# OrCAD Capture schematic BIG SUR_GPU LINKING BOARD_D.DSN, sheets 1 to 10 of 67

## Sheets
1 P01  Cover Page: title: Big Sur; rev: D; company: Quanta
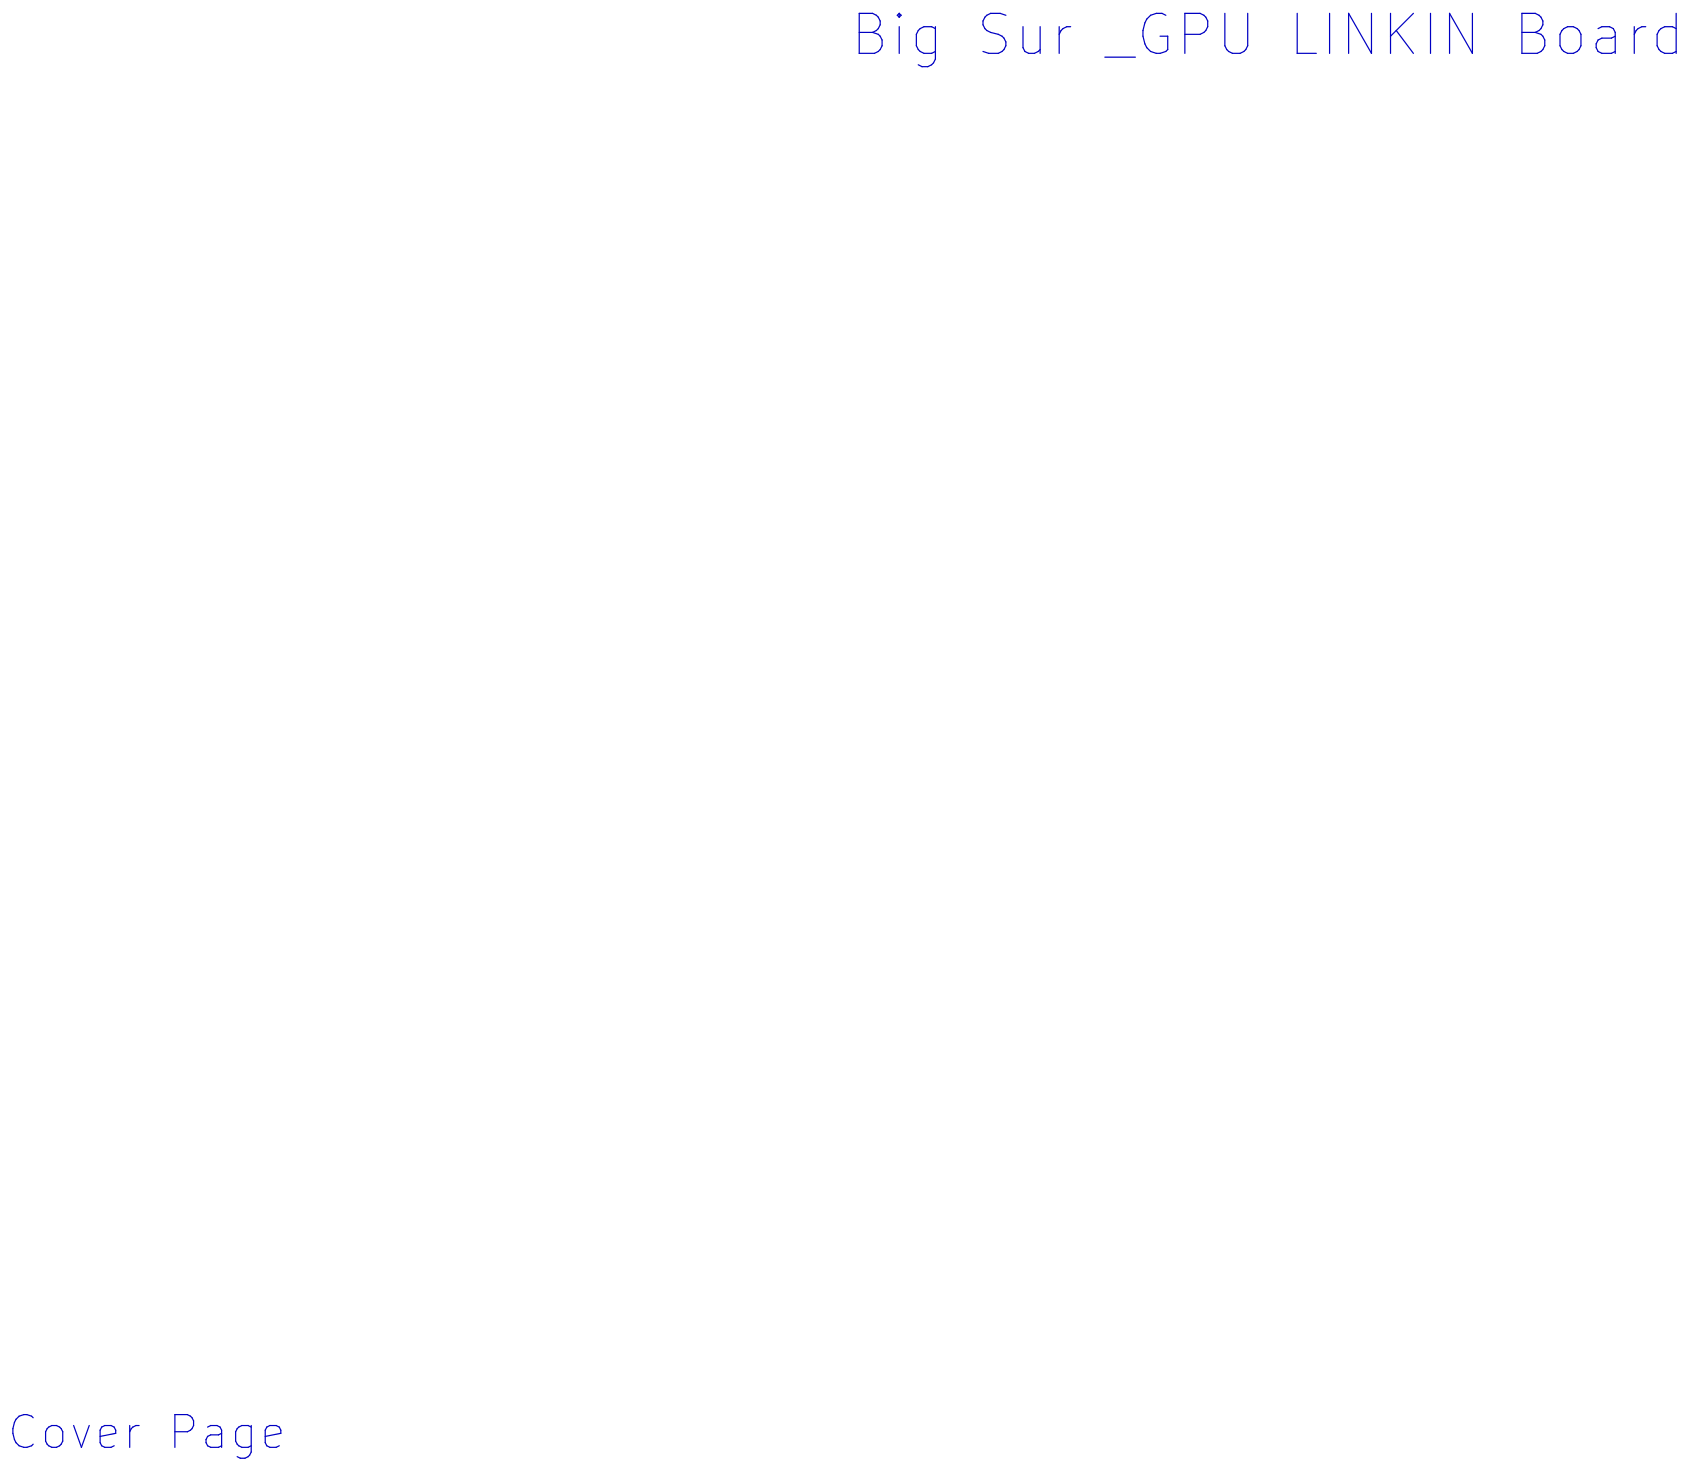
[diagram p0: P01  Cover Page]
2 P02  Index
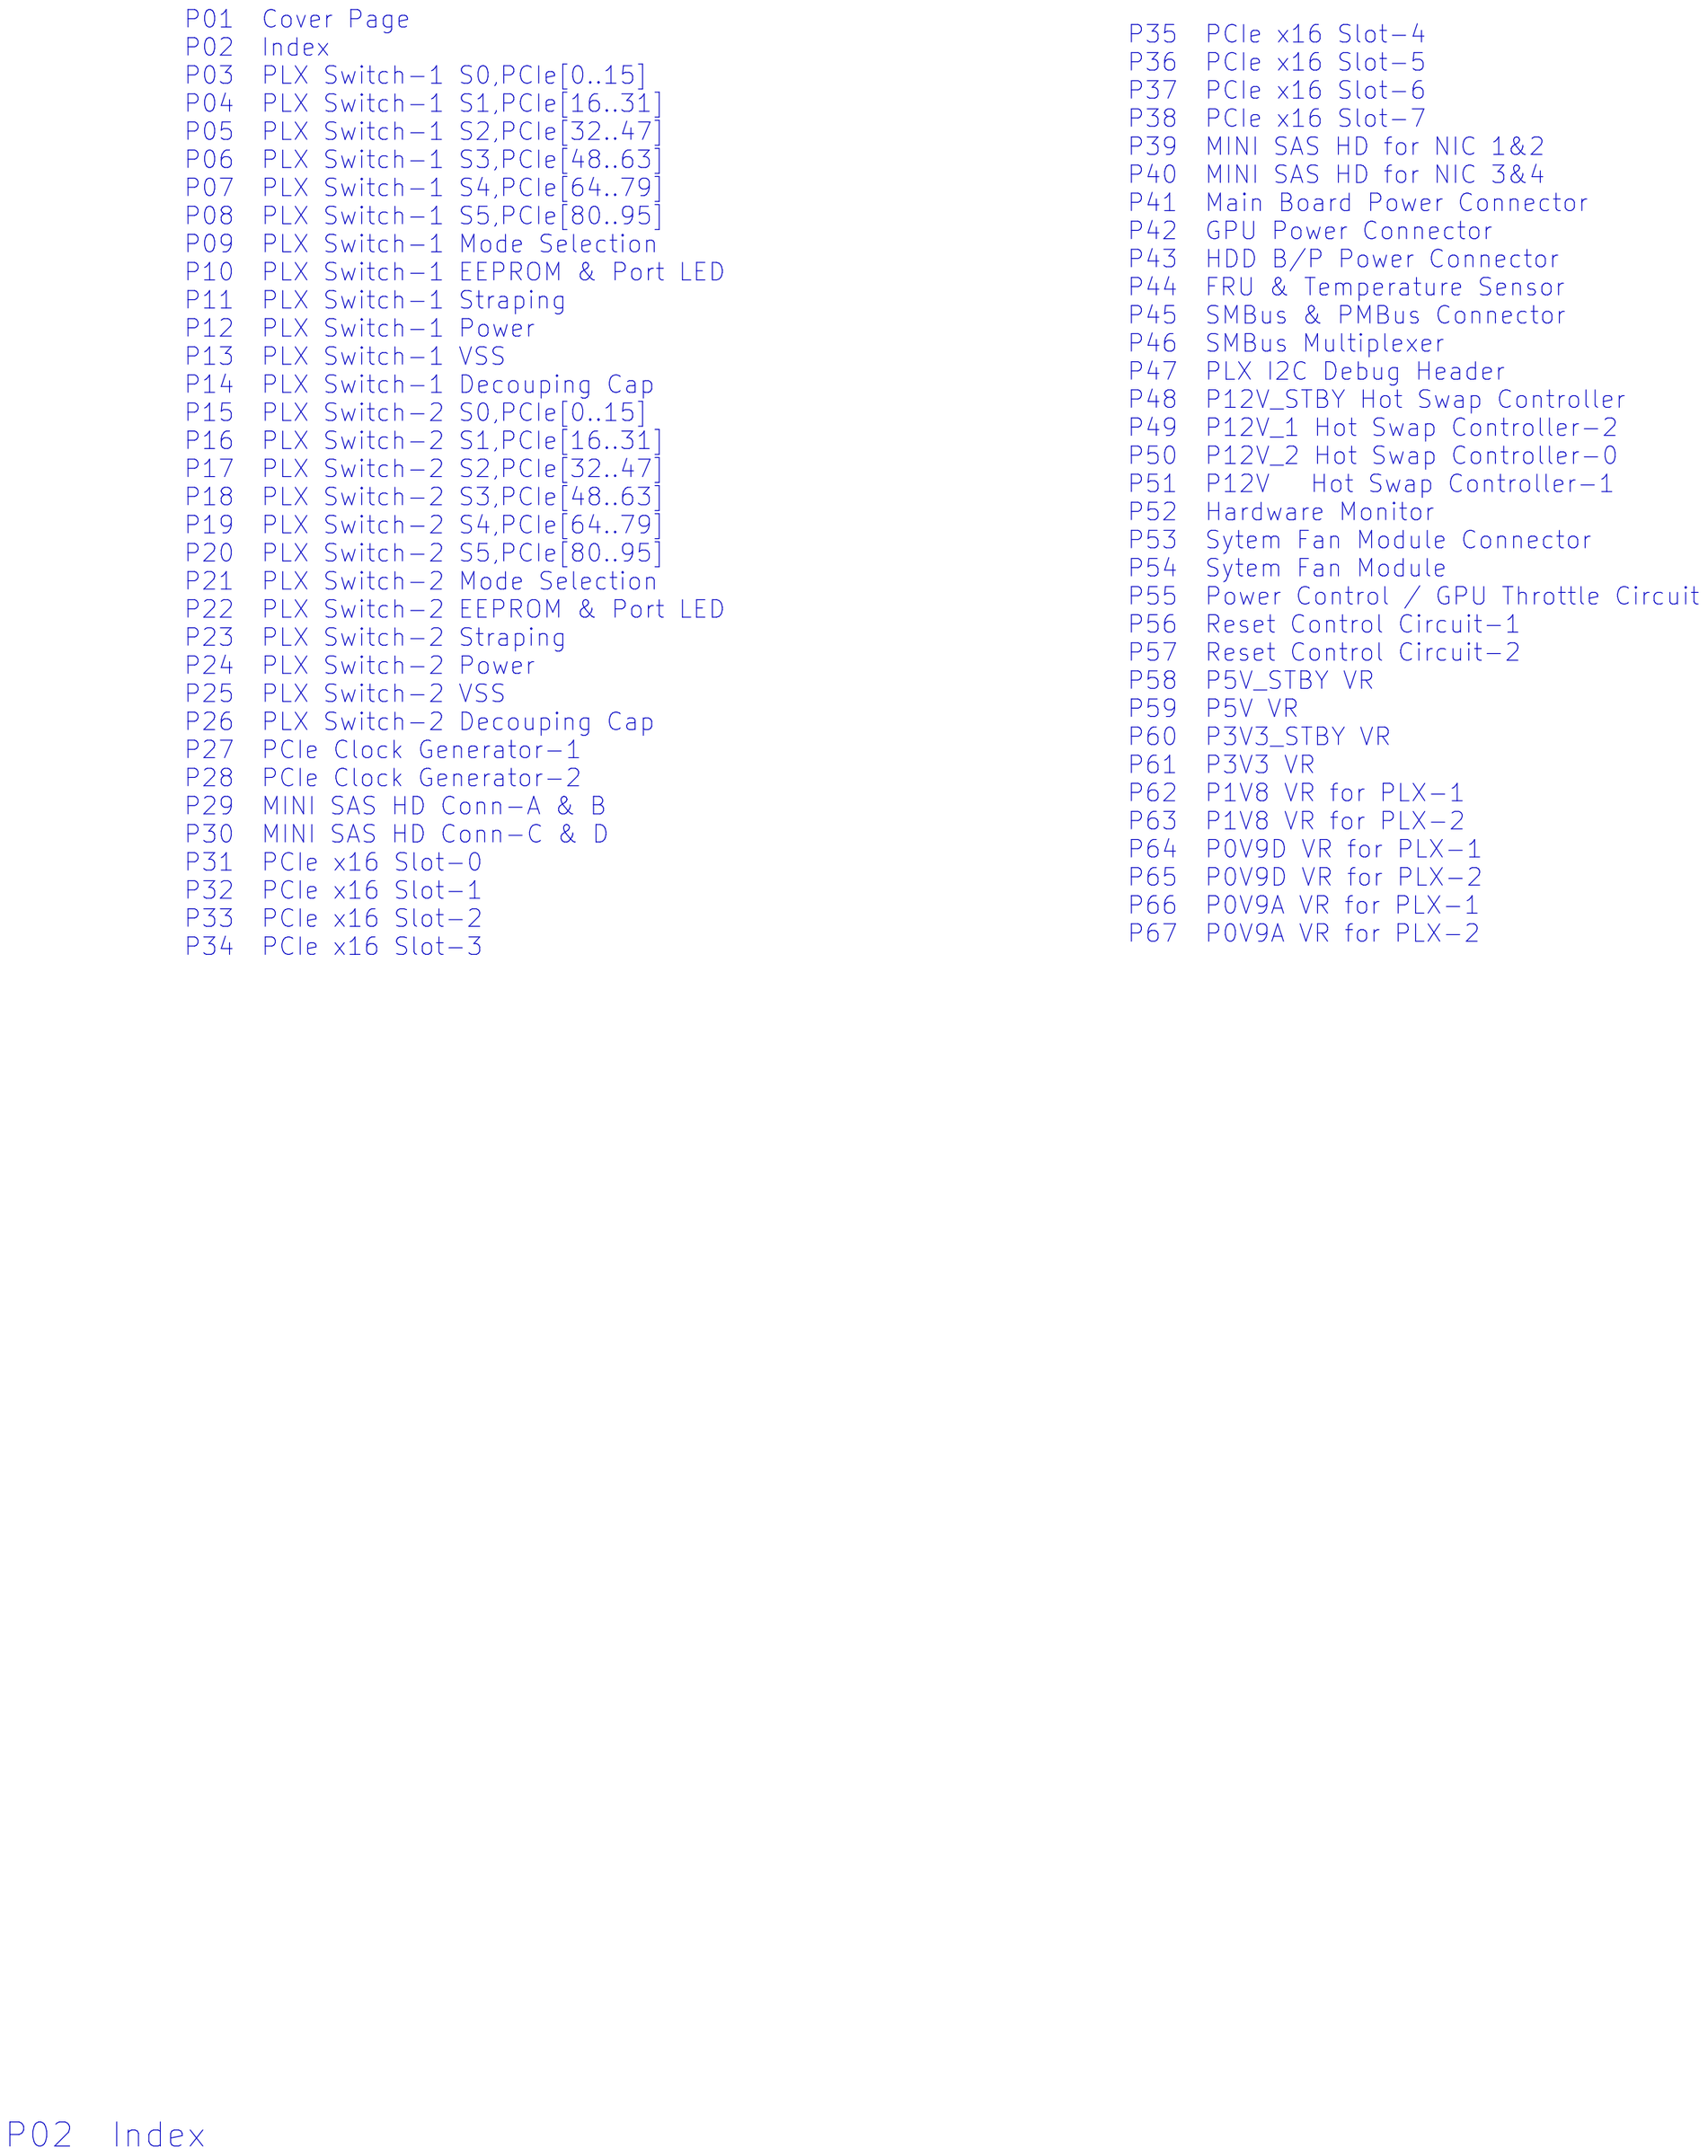
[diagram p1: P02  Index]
3 P03  PLX Switch-1 S0: size C
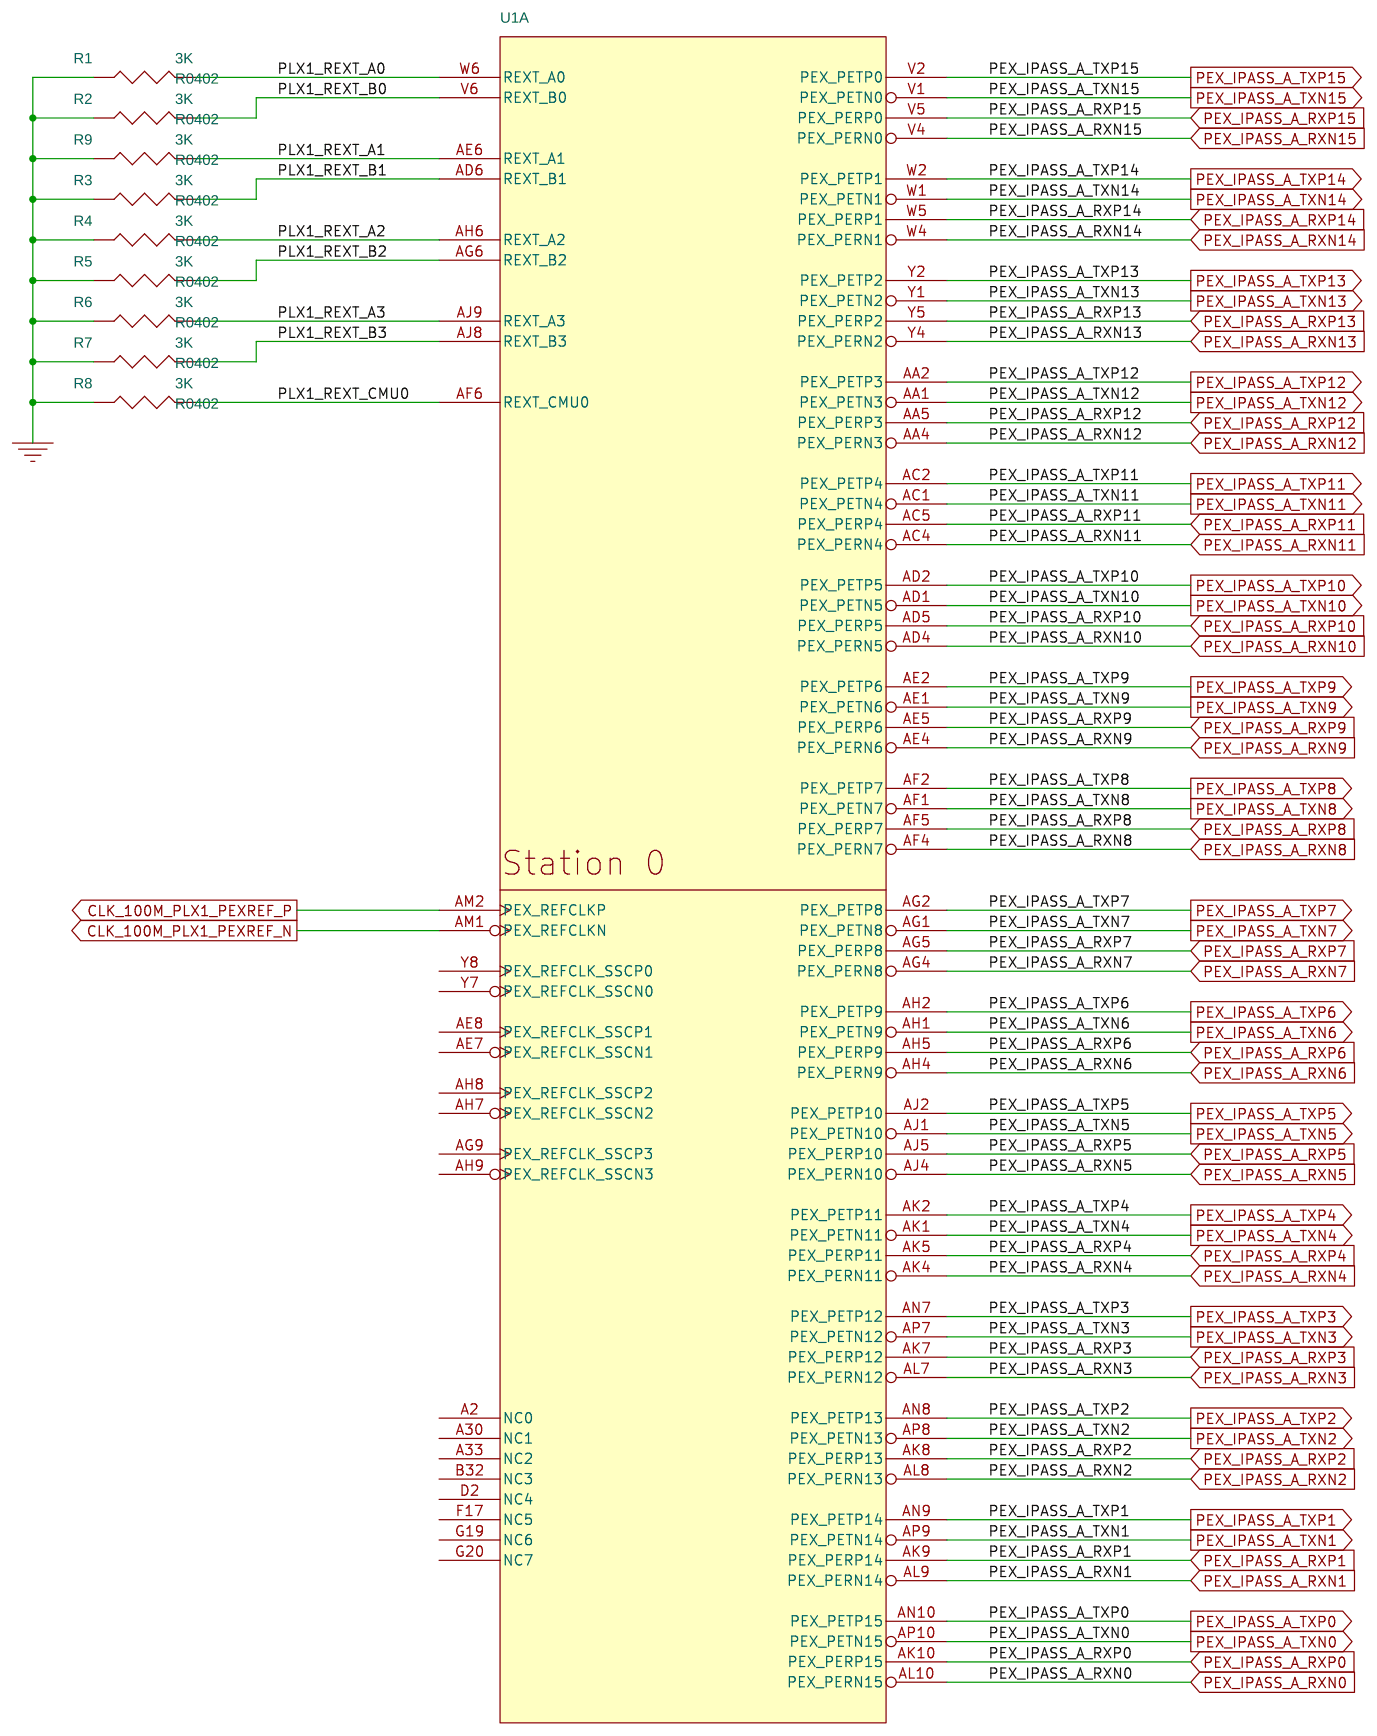
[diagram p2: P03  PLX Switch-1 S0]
4 P04  PLX Switch-1 S1: size C
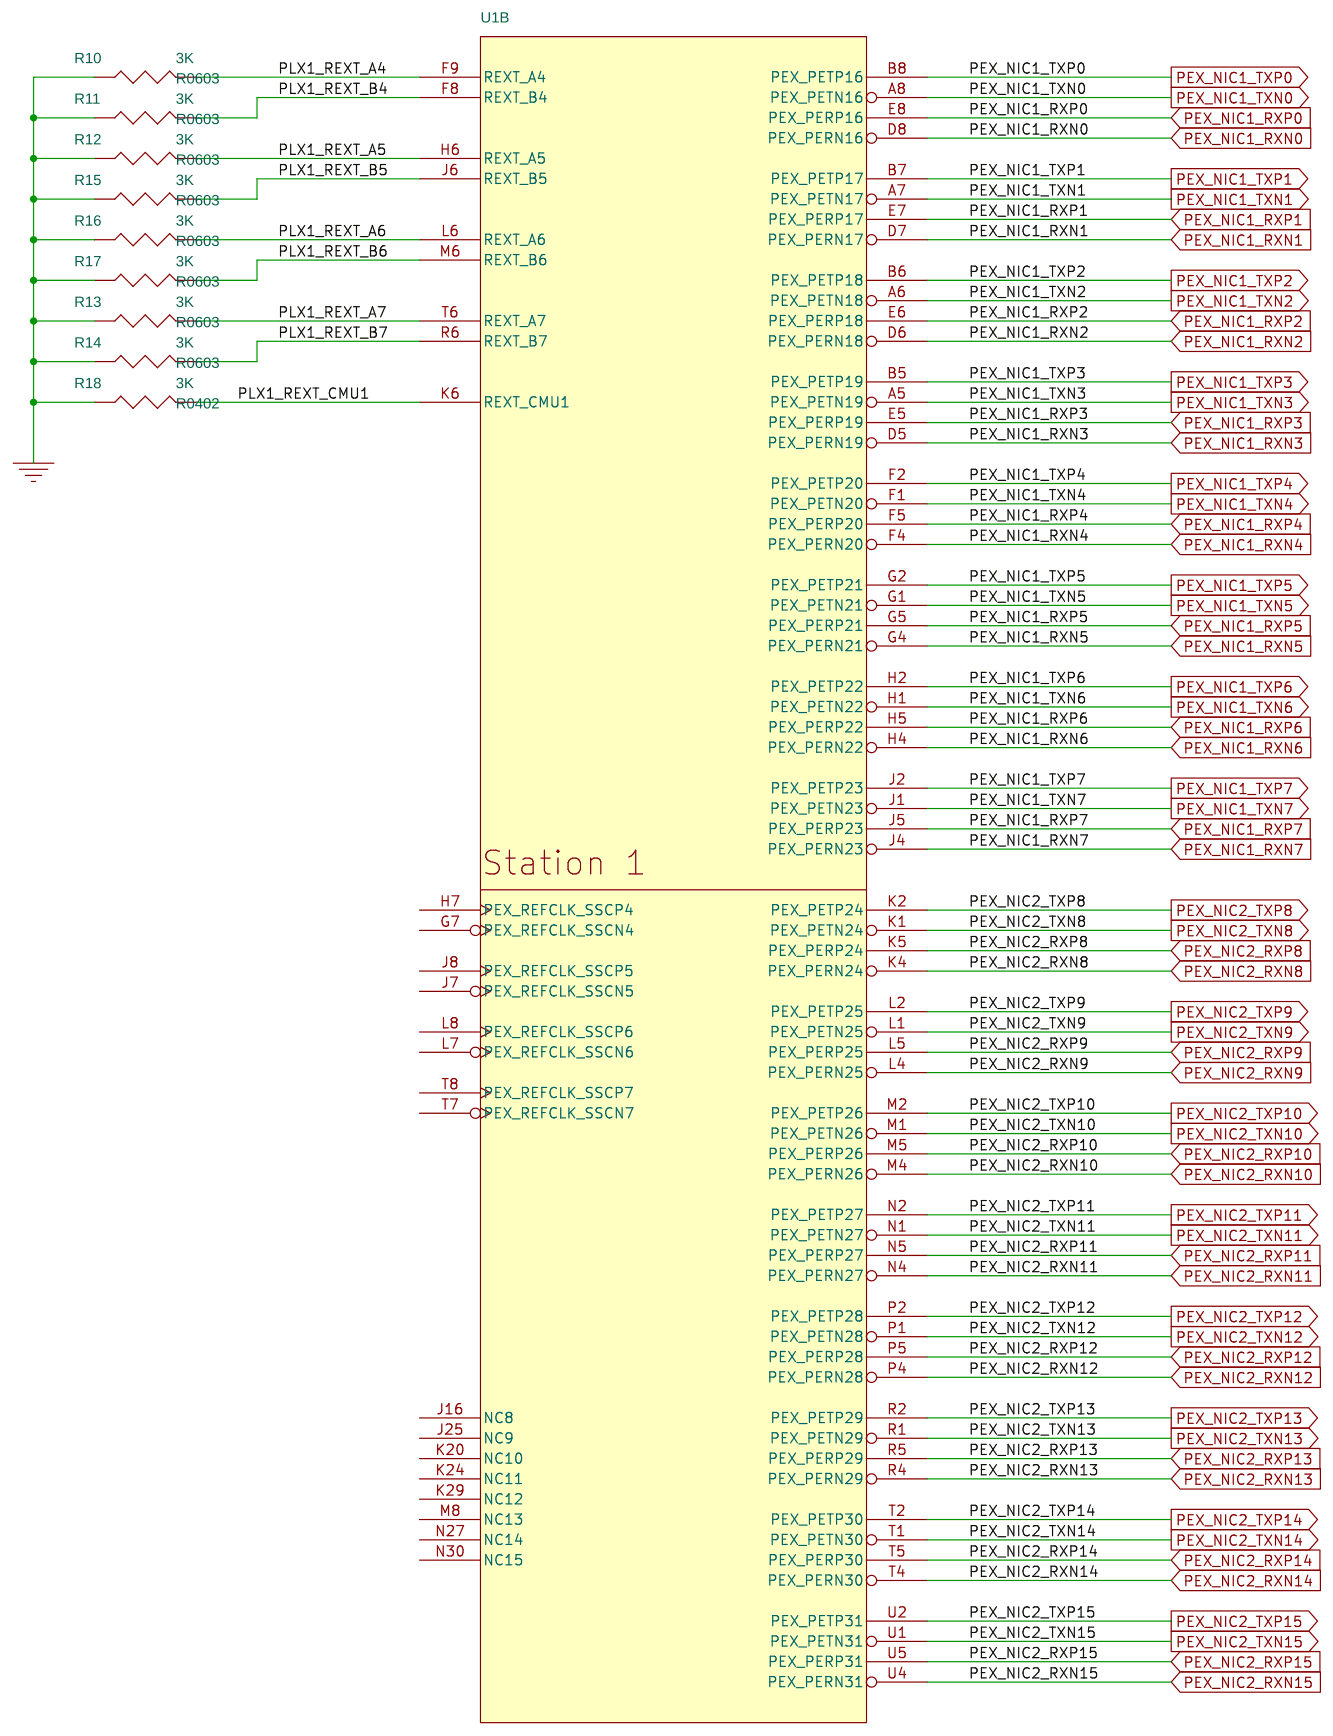
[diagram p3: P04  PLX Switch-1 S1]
5 P05  PLX Switch-1 S2: size C
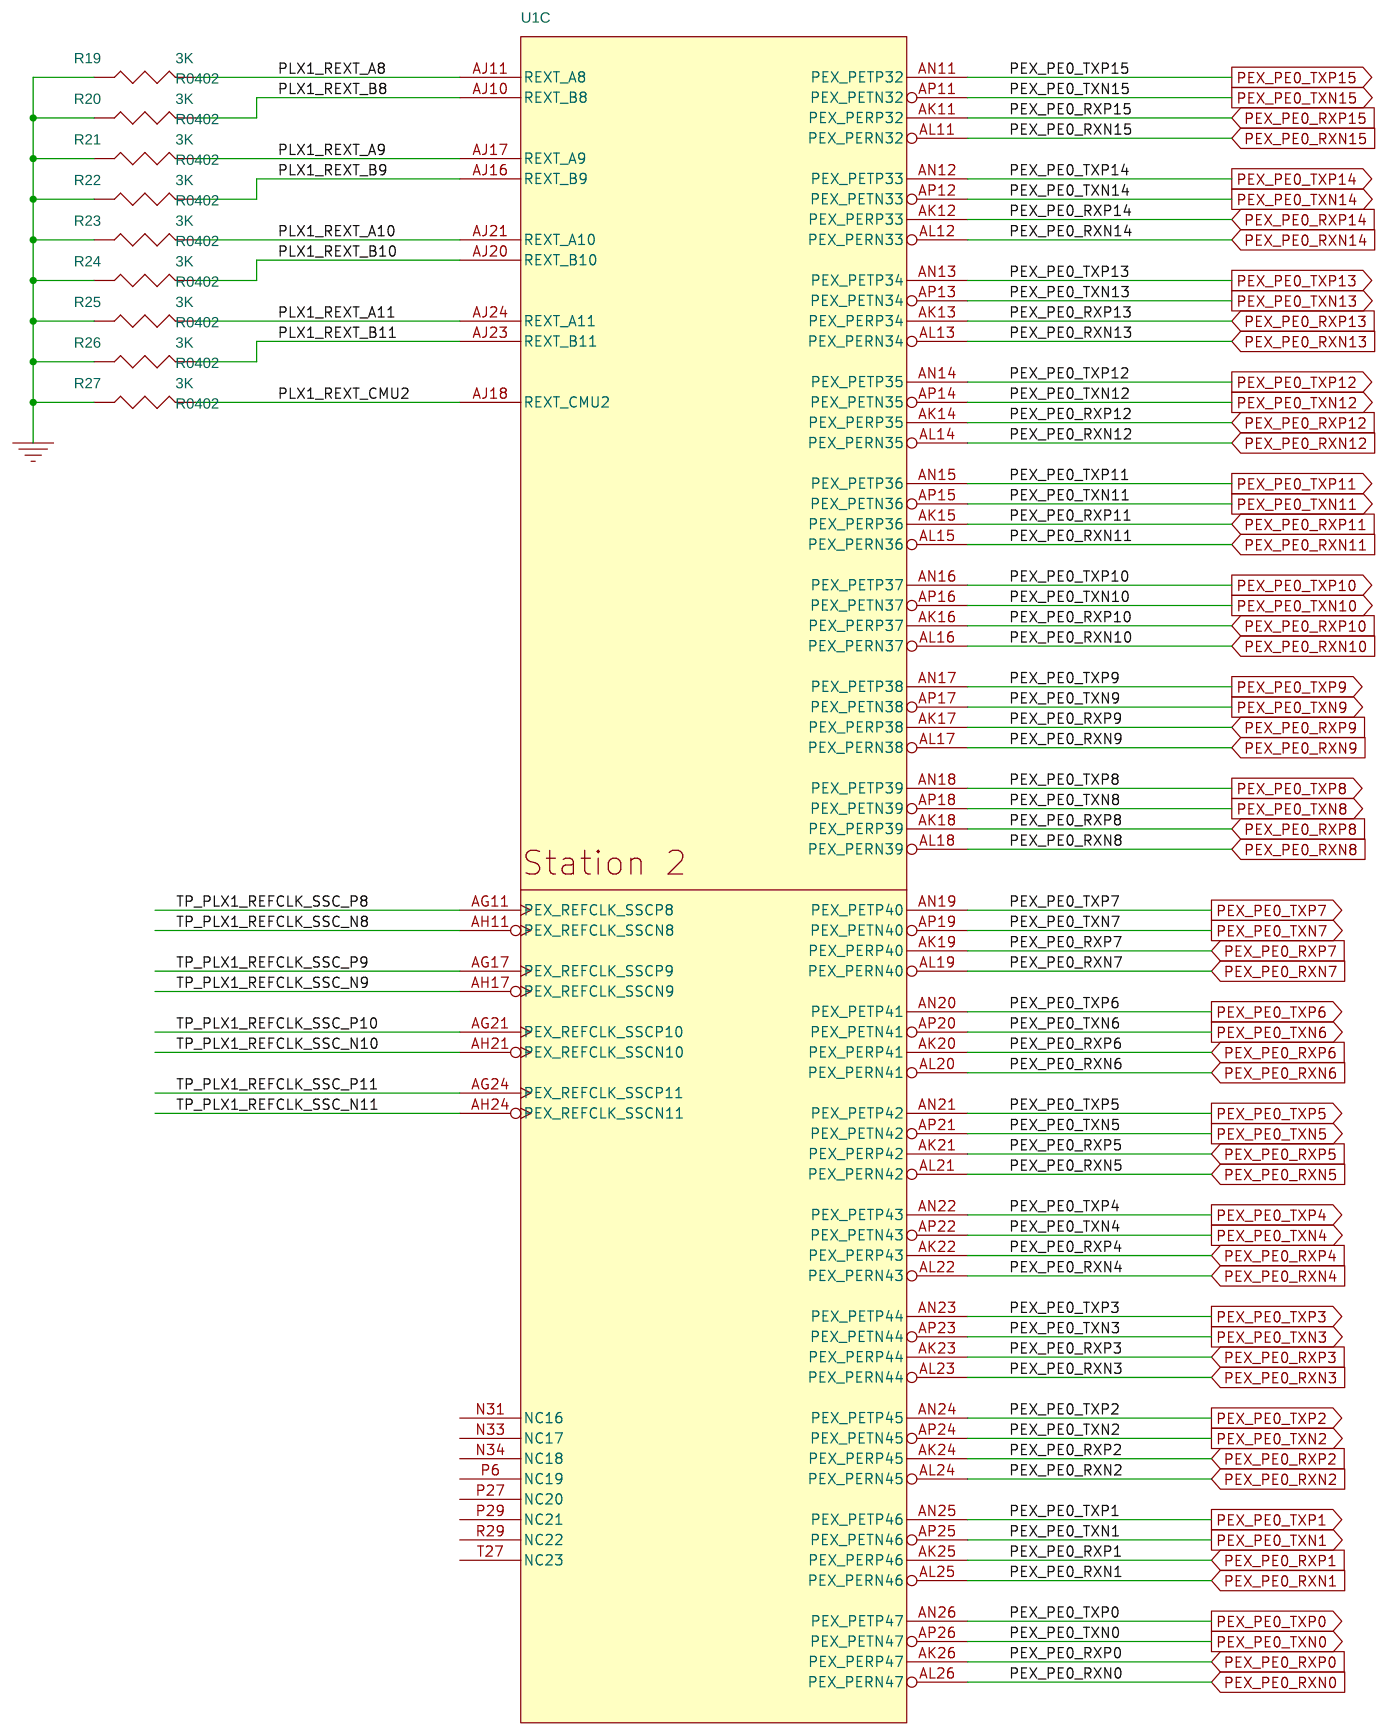
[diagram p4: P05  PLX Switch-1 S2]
6 P06  PLX Switch-1 S3: size Custom
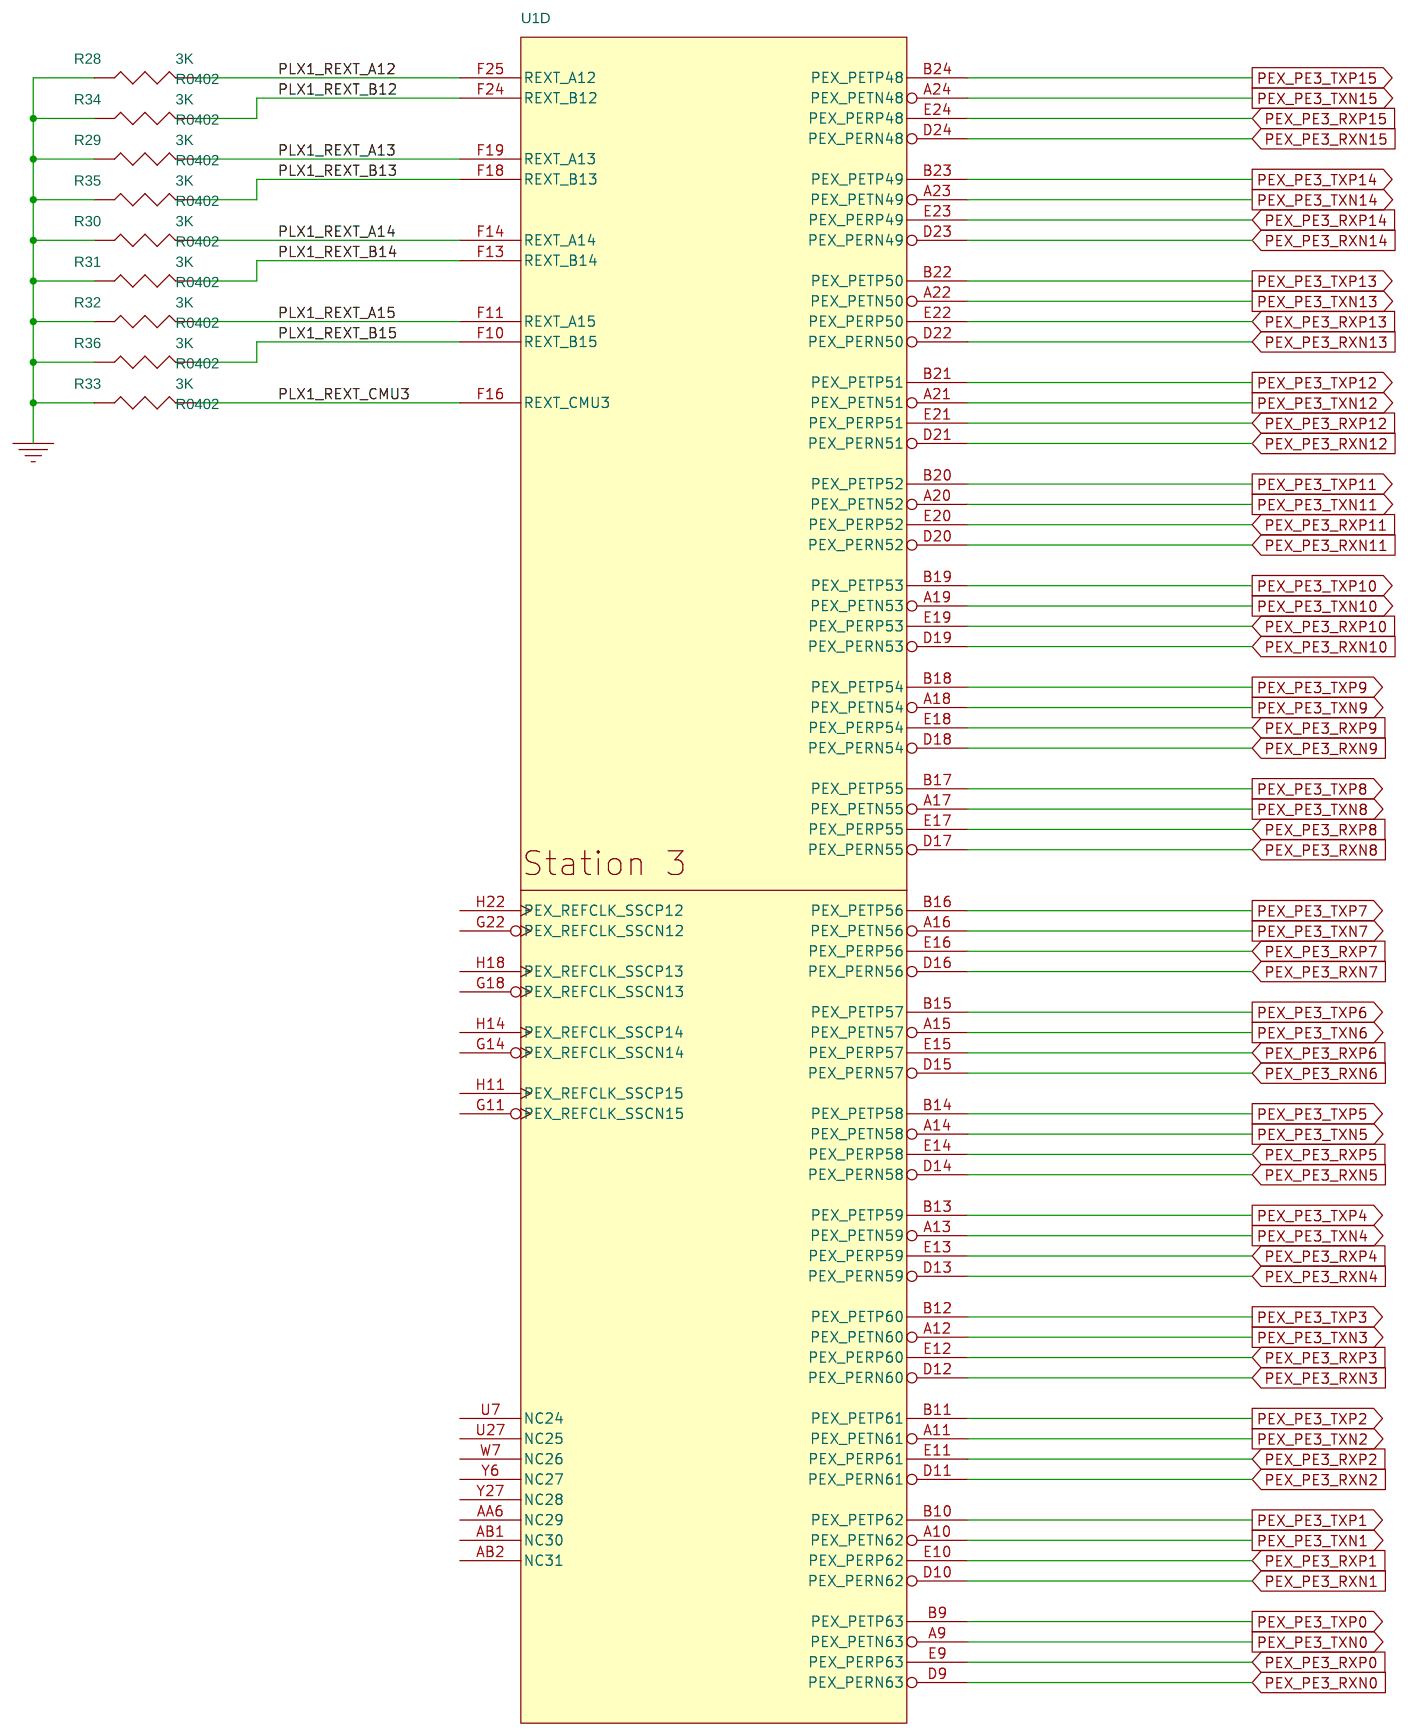
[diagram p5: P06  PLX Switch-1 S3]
7 P07  PLX Switch-1 S4: size Custom
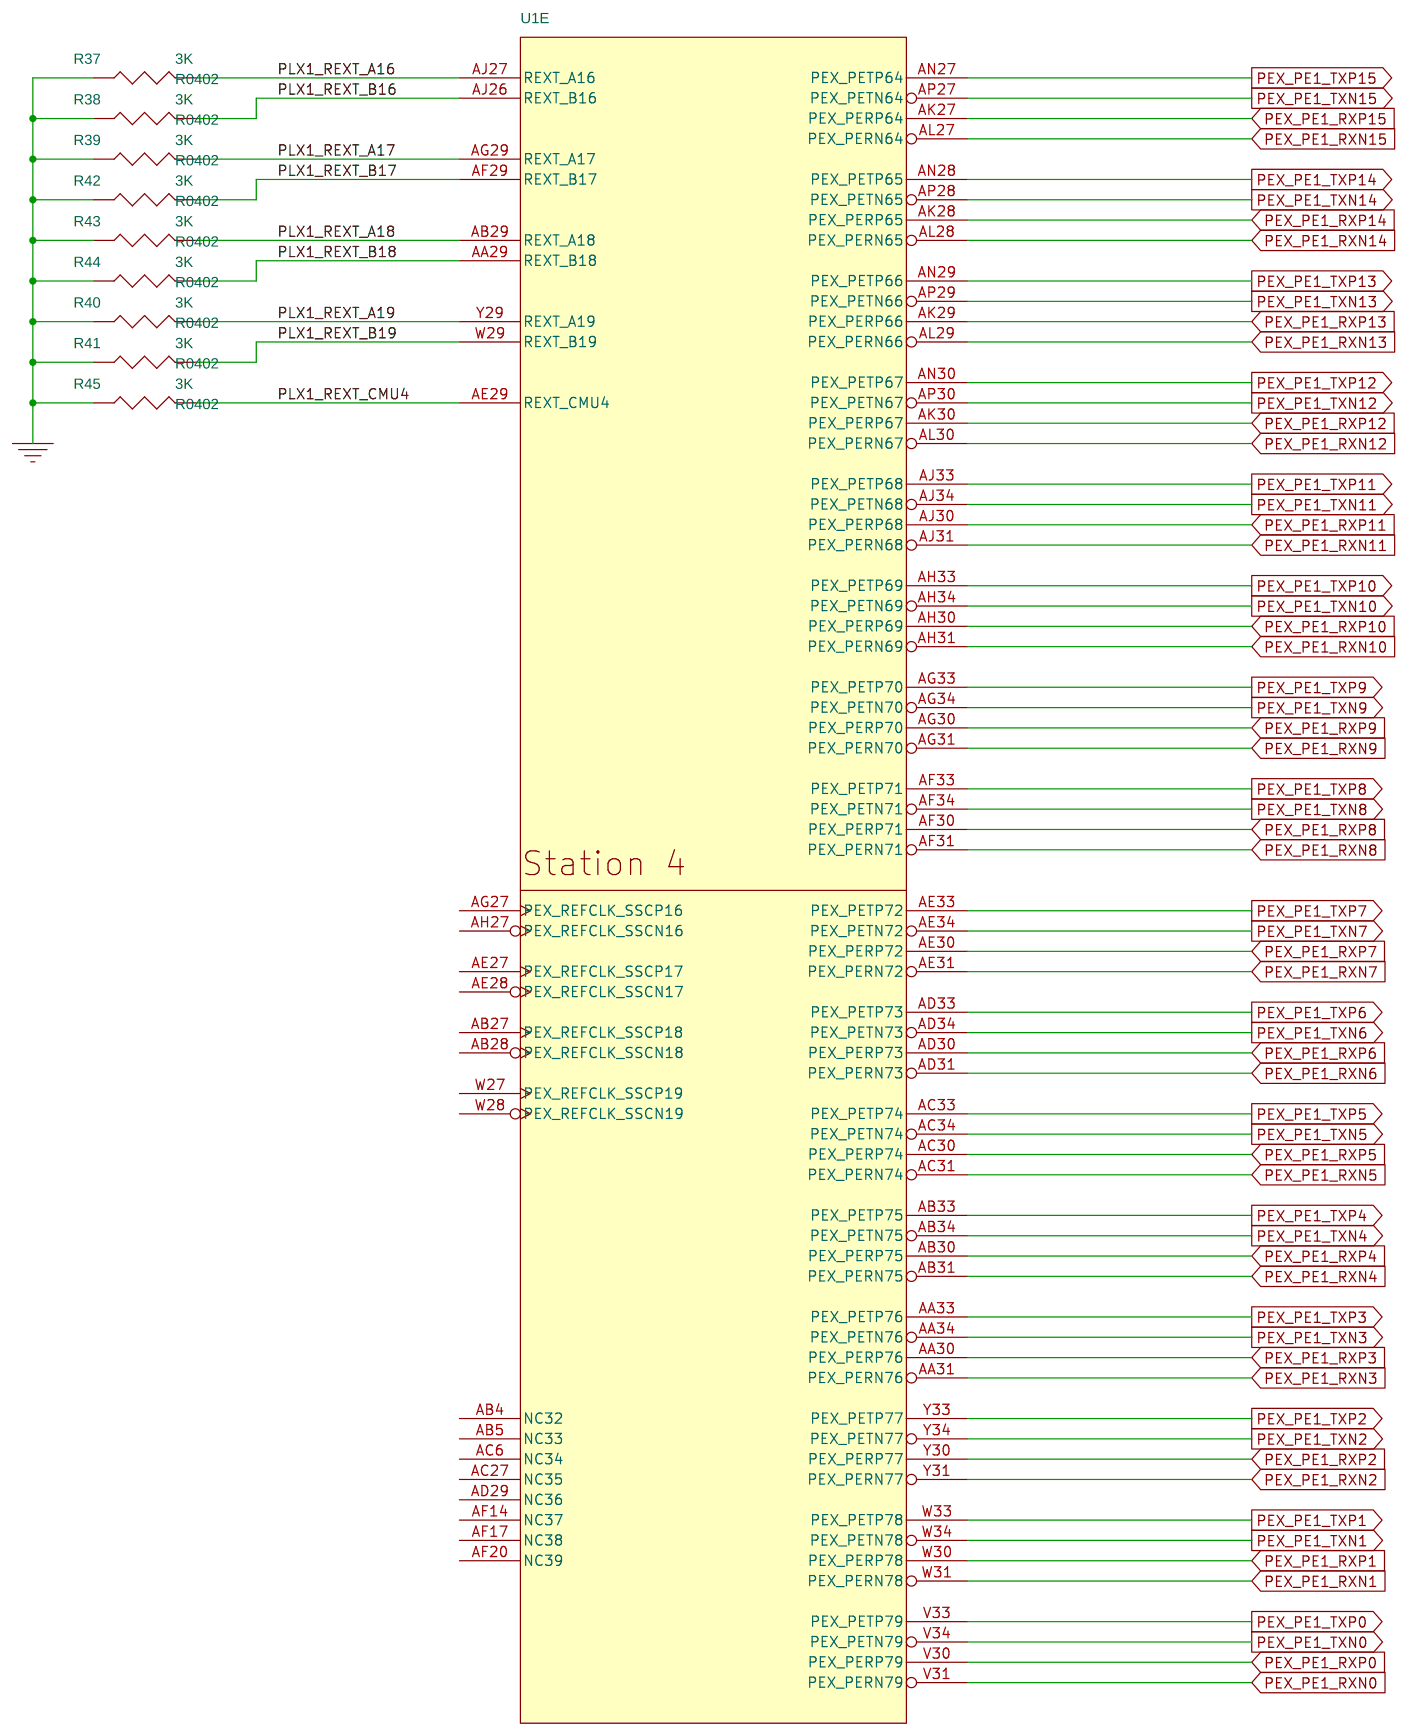
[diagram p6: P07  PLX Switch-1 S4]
8 P08  PLX Switch-1 S5: size Custom
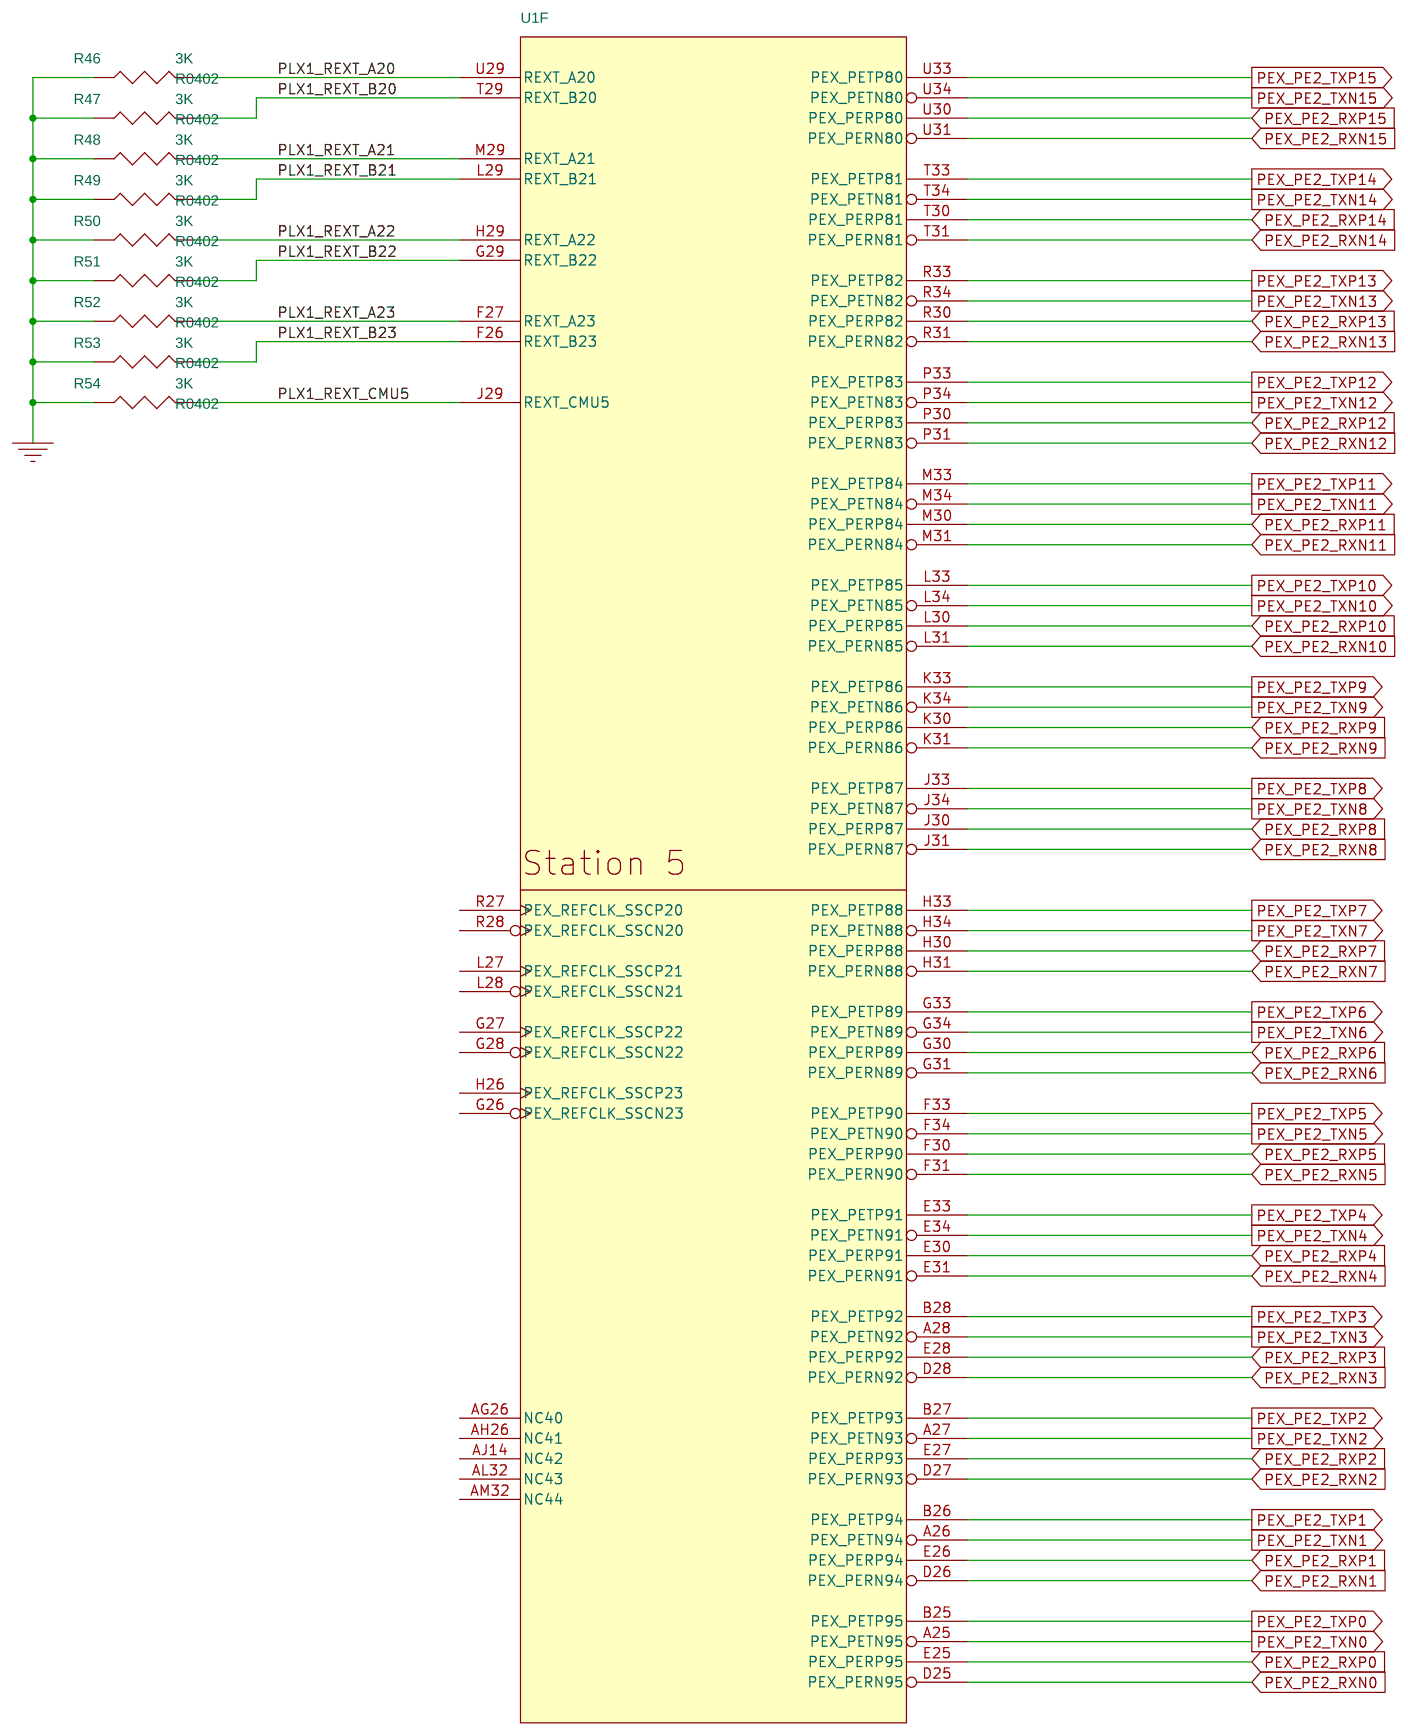
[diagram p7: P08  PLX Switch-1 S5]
9 P09  PLX Switch-1 Mode Select: size C
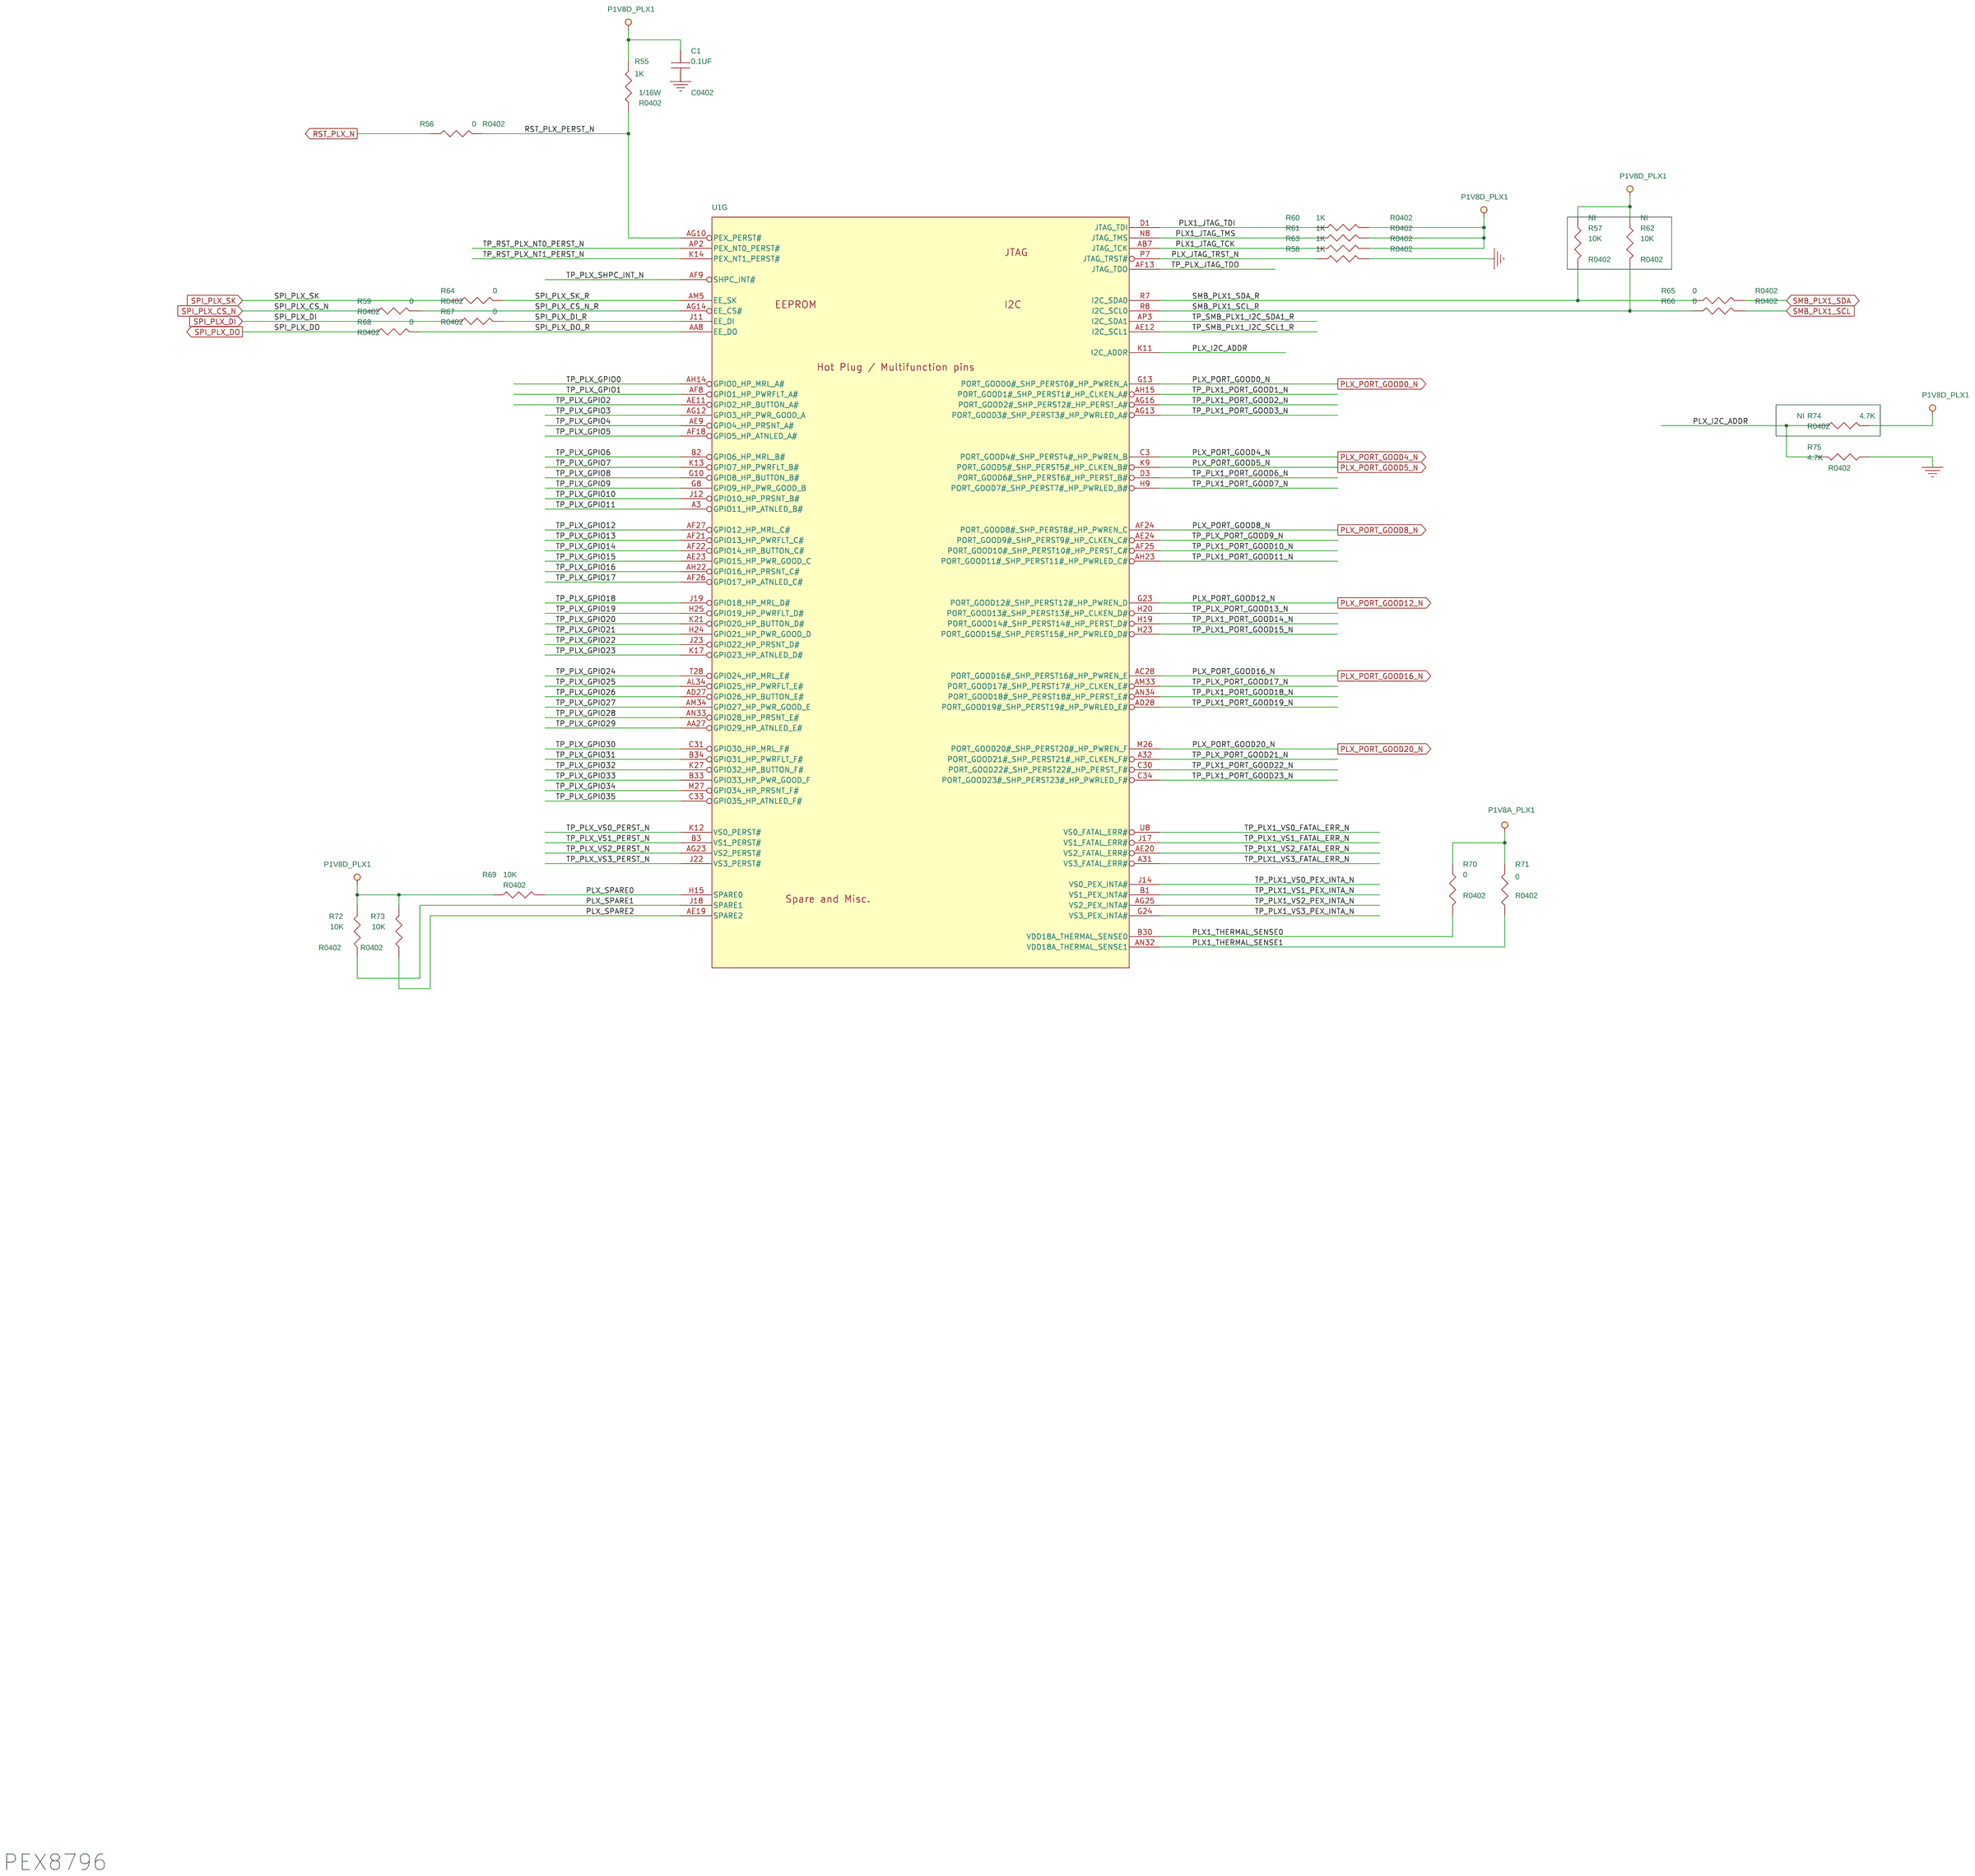
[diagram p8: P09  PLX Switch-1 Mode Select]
10 P10  PLX SW-1 EEPROM & Port LED: size C
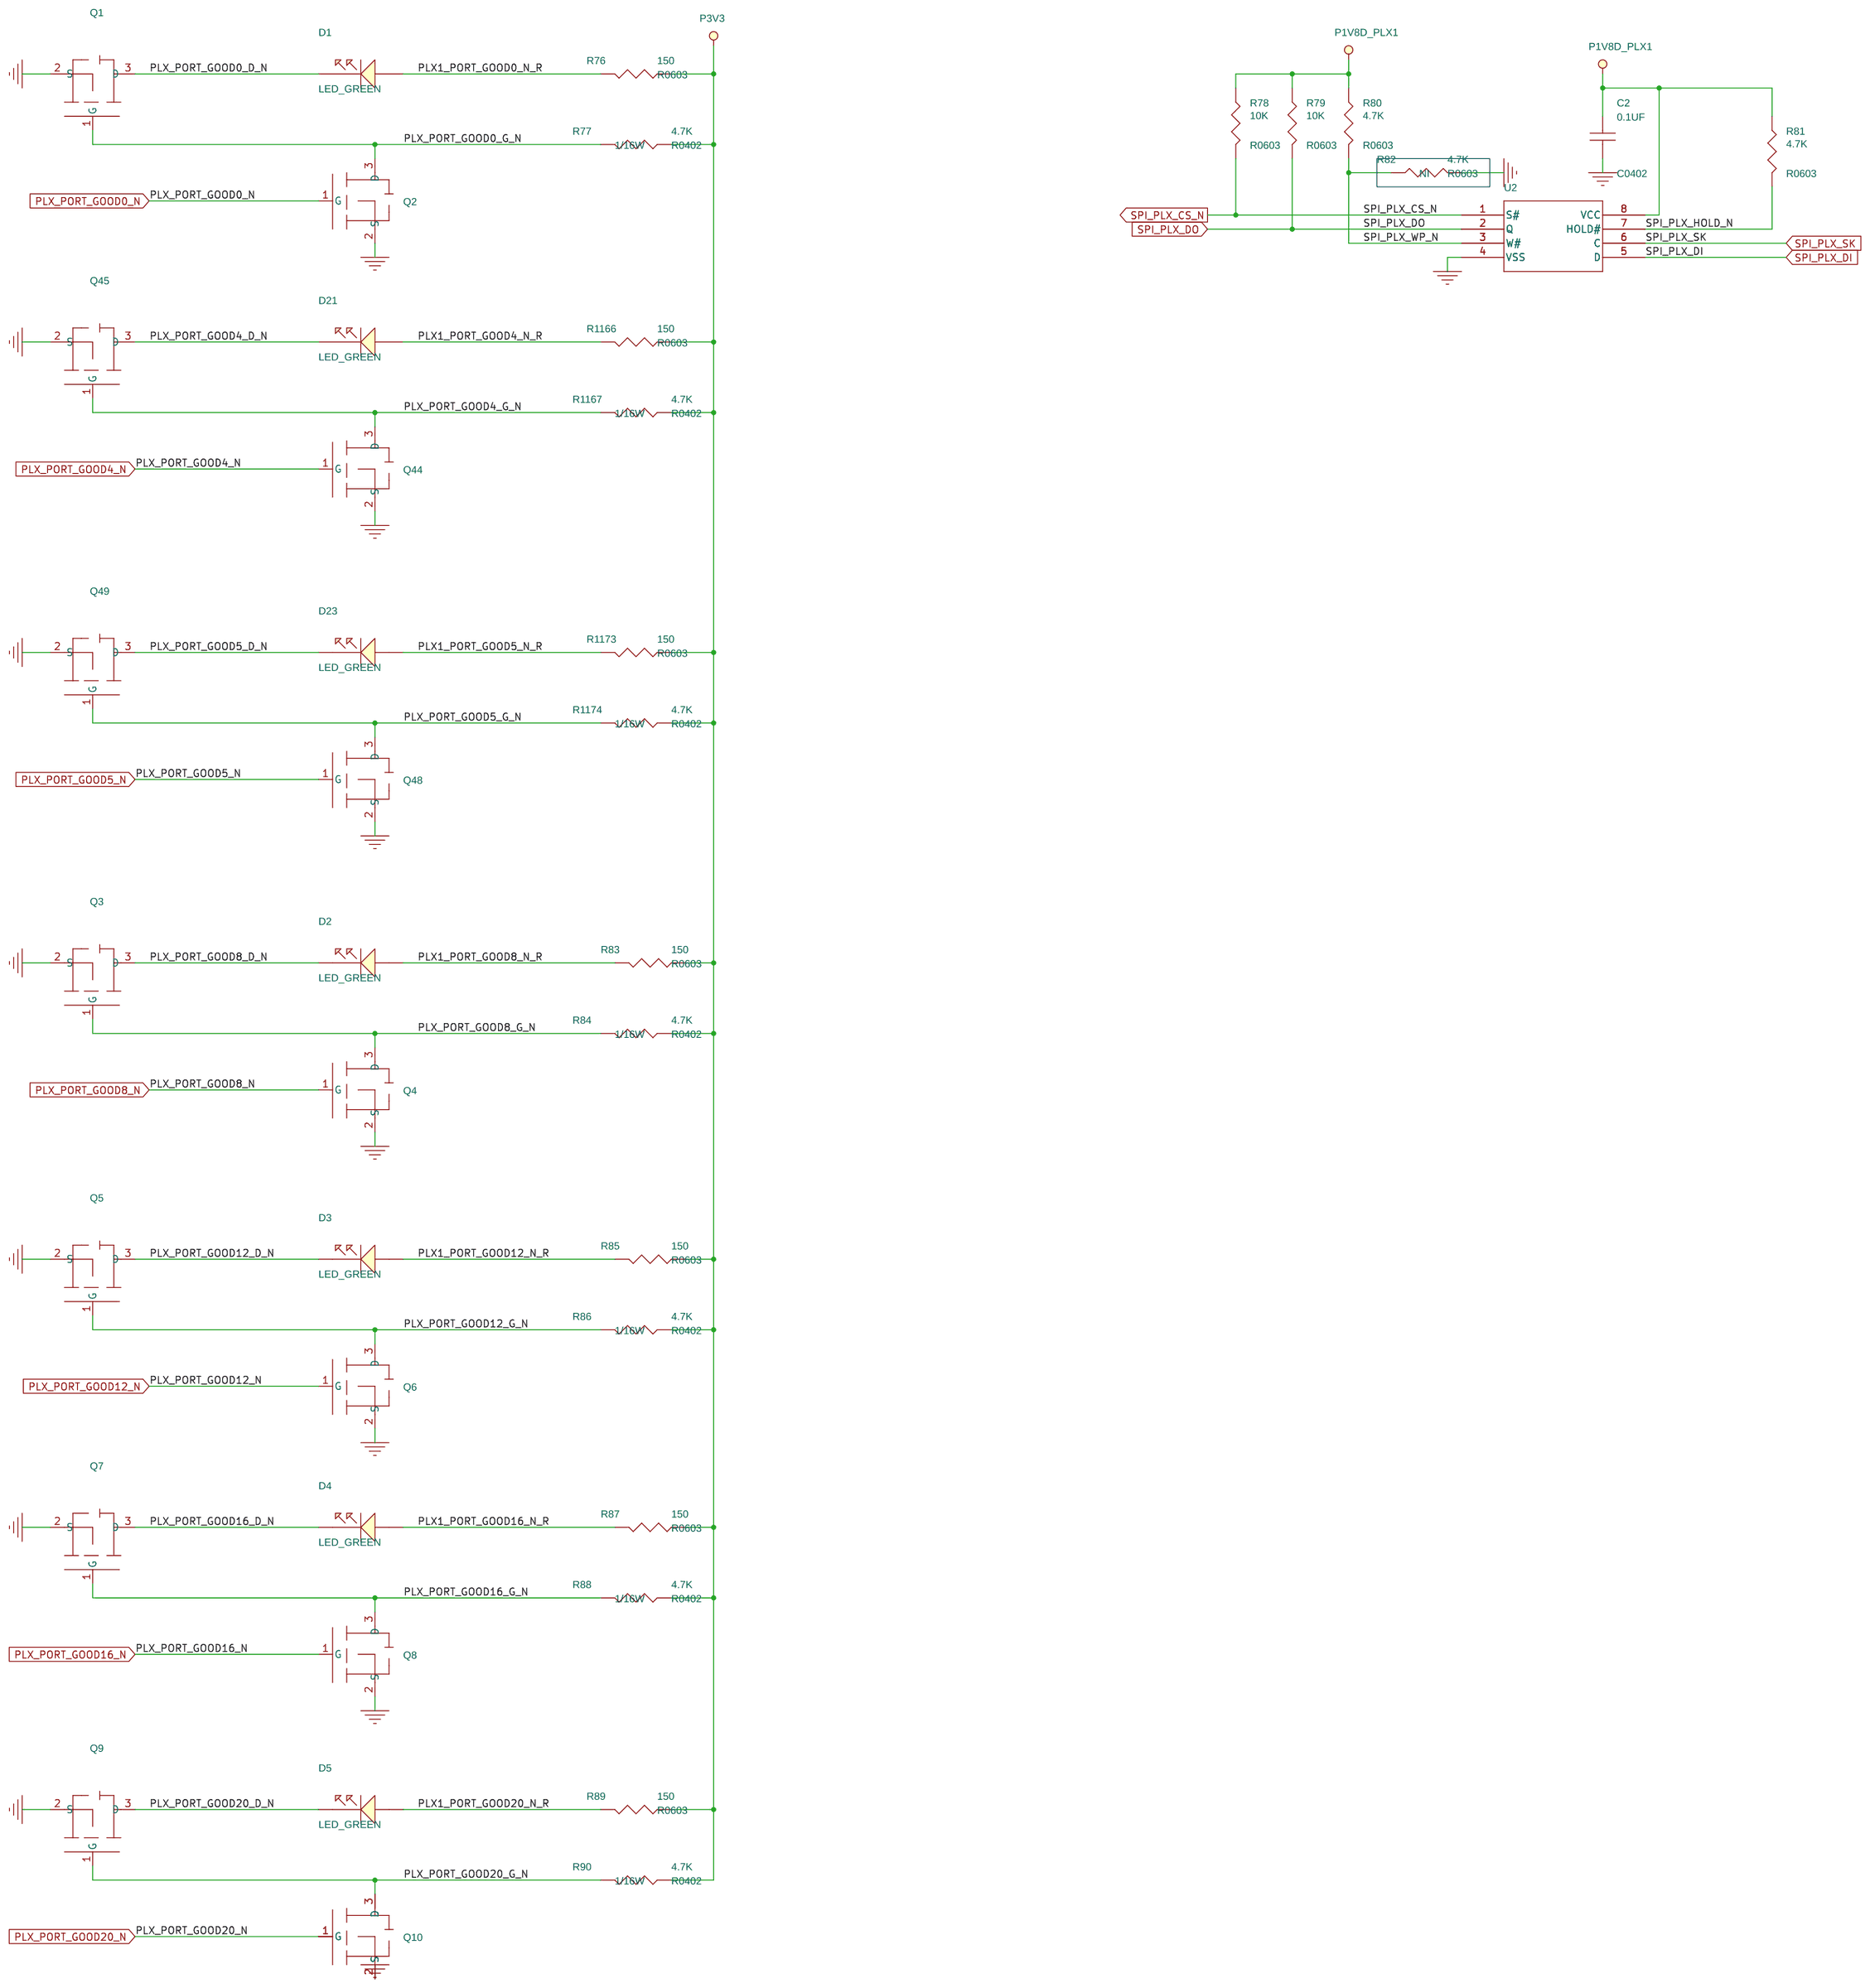
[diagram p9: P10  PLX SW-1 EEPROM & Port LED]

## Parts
sheet P03  PLX Switch-1 S0
R1  3K  [R0402]
R2  3K  [R0402]
R3  3K  [R0402]
R4  3K  [R0402]
R5  3K  [R0402]
R6  3K  [R0402]
R7  3K  [R0402]
R8  3K  [R0402]
R9  3K  [R0402]
sheet P04  PLX Switch-1 S1
R10  3K  [R0603]
R11  3K  [R0603]
R12  3K  [R0603]
R13  3K  [R0603]
R14  3K  [R0603]
R15  3K  [R0603]
R16  3K  [R0603]
R17  3K  [R0603]
R18  3K  [R0402]
sheet P05  PLX Switch-1 S2
R19  3K  [R0402]
R20  3K  [R0402]
R21  3K  [R0402]
R22  3K  [R0402]
R23  3K  [R0402]
R24  3K  [R0402]
R25  3K  [R0402]
R26  3K  [R0402]
R27  3K  [R0402]
sheet P06  PLX Switch-1 S3
R28  3K  [R0402]
R29  3K  [R0402]
R30  3K  [R0402]
R31  3K  [R0402]
R32  3K  [R0402]
R33  3K  [R0402]
R34  3K  [R0402]
R35  3K  [R0402]
R36  3K  [R0402]
sheet P07  PLX Switch-1 S4
R37  3K  [R0402]
R38  3K  [R0402]
R39  3K  [R0402]
R40  3K  [R0402]
R41  3K  [R0402]
R42  3K  [R0402]
R43  3K  [R0402]
R44  3K  [R0402]
R45  3K  [R0402]
sheet P08  PLX Switch-1 S5
R46  3K  [R0402]
R47  3K  [R0402]
R48  3K  [R0402]
R49  3K  [R0402]
R50  3K  [R0402]
R51  3K  [R0402]
R52  3K  [R0402]
R53  3K  [R0402]
R54  3K  [R0402]
sheet P09  PLX Switch-1 Mode Select
C1  0.1UF  [C0402]
R55  1K  [R0402]
R56  0  [R0402]
R57  10K  [R0402]
R58  1K  [R0402]
R59  0  [R0402]
R60  1K  [R0402]
R61  1K  [R0402]
R62  10K  [R0402]
R63  1K  [R0402]
R64  0  [R0402]
R65  0  [R0402]
R66  0  [R0402]
R67  0  [R0402]
R68  0  [R0402]
R69  10K  [R0402]
R70  0  [R0402]
R71  0  [R0402]
R72  10K  [R0402]
R73  10K  [R0402]
R74  4.7K  [R0402]
R75  4.7K  [R0402]
sheet P10  PLX SW-1 EEPROM & Port LED
C2  0.1UF  [C0402]
D1  LED_GREEN  [LED_1221B]
D2  LED_GREEN  [LED_1221B]
D3  LED_GREEN  [LED_1221B]
D4  LED_GREEN  [LED_1221B]
D5  LED_GREEN  [LED_1221B]
D21  LED_GREEN  [LED_1221B]
D23  LED_GREEN  [LED_1221B]
Q1  BSS138LT1G  [SOT23_123]
Q2  BSS138LT1G  [SOT23_123]
Q3  BSS138LT1G  [SOT23_123]
Q4  BSS138LT1G  [SOT23_123]
Q5  BSS138LT1G  [SOT23_123]
Q6  BSS138LT1G  [SOT23_123]
Q7  BSS138LT1G  [SOT23_123]
Q8  BSS138LT1G  [SOT23_123]
Q9  BSS138LT1G  [SOT23_123]
Q10  BSS138LT1G  [SOT23_123]
Q44  BSS138LT1G  [SOT23_123]
Q45  BSS138LT1G  [SOT23_123]
Q48  BSS138LT1G  [SOT23_123]
Q49  BSS138LT1G  [SOT23_123]
R76  150  [R0603]
R77  4.7K  [R0402]
R78  10K  [R0603]
R79  10K  [R0603]
R80  4.7K  [R0603]
R81  4.7K  [R0603]
R82  4.7K  [R0603]
R83  150  [R0603]
R84  4.7K  [R0402]
R85  150  [R0603]
R86  4.7K  [R0402]
R87  150  [R0603]
R88  4.7K  [R0402]
R89  150  [R0603]
R90  4.7K  [R0402]
R1166  150  [R0603]
R1167  4.7K  [R0402]
R1173  150  [R0603]
R1174  4.7K  [R0402]
U2  IC  [SOIC8XH]
sheet P11  PLX Switch-1 Straping
U1  PLX  [BGA1156]  (sections A,B,C,D,E,F,G,H,I,J,K,L)

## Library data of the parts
R1-R9 R18-R56 R58-R61 R63-R73 R75 R77 R84 R86 R88 R90 R1167 R1174 = R: Part_Type: *LF_Resistor; WATTAGE: 1/16W
R10-R17 R76 R78-R81 R83 R85 R87 R89 R1166 R1173 = R: Part_Type: *LF_Resistor; WATTAGE: 1/10W
C1 C2 = CAP_NP: Part_Type: *LF_C0402
R57 R62 R74 = R: Not_insert: NI; Part_Type: *LF_Resistor; WATTAGE: 1/16W
D1-D5 D21 D23 = LED_12: Part_Type: Semiconductor
Q1-Q10 Q44 Q45 Q48 Q49 = BSS123: Part_Type: *LF_Semiconductor
R82 = R: Not_insert: NI; Part_Type: *LF_Resistor; WATTAGE: 1/10W
U2 = M95512RMN6TP: Part_Type: *LF_Chipset
U1 = PEX8796AA80BIG: Part_Type: *LF_Chipset

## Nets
GND: C1.2 C2.2 Q1.2(S) Q2.2(S) Q3.2(S) Q4.2(S) Q5.2(S) Q6.2(S) Q7.2(S) Q8.2(S) Q9.2(S) Q10.2(S) Q44.2(S) Q45.2(S) Q48.2(S) Q49.2(S) R1.1 R2.1 R3.1 R4.1 R5.1 R6.1 R7.1 R8.1 R9.1 R10.1 R11.1 R12.1 R13.1 R14.1 R15.1 R16.1 R17.1 R18.1 R19.1 R20.1 R21.1 R22.1 R23.1 R24.1 R25.1 R26.1 R27.1 R28.1 R29.1 R30.1 R31.1 R32.1 R33.1 R34.1 R35.1 R36.1 R37.1 R38.1 R39.1 R40.1 R41.1 R42.1 R43.1 R44.1 R45.1 R46.1 R47.1 R48.1 R49.1 R50.1 R51.1 R52.1 R53.1 R54.1 R58.1 R75.1 R82.2 U2.4(VSS) ; also on sheet 11 12 13 14 15 16 17 18 19 20 21 22 23 24 25 26 27 28 29 30 31 32 33 34 35 36 37 38 39 40 41 42 43 44 45 46 47 48 49 50 51 52 53 54 55 56 57 58 59 60 61 62 63 64 65 66 67
P1V8A_PLX1: R70.2 R71.2 ; also on sheet 12 14 60
P1V8D_PLX1: C1.1 C2.1 R55.2 R57.1 R60.1 R61.1 R62.1 R63.1 R69.2 R72.1 R73.1 R74.2 R78.1 R79.1 R80.1 R81.1 U2.8(VCC) ; also on sheet 11 12 14 46 51 60
P3V3: R76.1 R77.1 R83.1 R84.1 R85.1 R86.1 R87.1 R88.1 R89.1 R90.1 R1166.1 R1167.1 R1173.1 R1174.1 ; also on sheet 22 27 28 31 32 33 34 35 36 37 38 41 44 51 53 59 60 61 62 63 64 65 66
CLK_100M_PLX1_PEXREF_N: U1.AM1(PEX_REFCLKN) ; also on sheet 27
CLK_100M_PLX1_PEXREF_P: U1.AM2(PEX_REFCLKP) ; also on sheet 27
PEX_IPASS_A_RXN0: U1.AL10(PEX_PERN15) ; also on sheet 29
PEX_IPASS_A_RXN1: U1.AL9(PEX_PERN14) ; also on sheet 29
PEX_IPASS_A_RXN2: U1.AL8(PEX_PERN13) ; also on sheet 29
PEX_IPASS_A_RXN3: U1.AL7(PEX_PERN12) ; also on sheet 29
PEX_IPASS_A_RXN4: U1.AK4(PEX_PERN11) ; also on sheet 29
PEX_IPASS_A_RXN5: U1.AJ4(PEX_PERN10) ; also on sheet 29
PEX_IPASS_A_RXN6: U1.AH4(PEX_PERN9) ; also on sheet 29
PEX_IPASS_A_RXN7: U1.AG4(PEX_PERN8) ; also on sheet 29
PEX_IPASS_A_RXN8: U1.AF4(PEX_PERN7) ; also on sheet 29
PEX_IPASS_A_RXN9: U1.AE4(PEX_PERN6) ; also on sheet 29
PEX_IPASS_A_RXN10: U1.AD4(PEX_PERN5) ; also on sheet 29
PEX_IPASS_A_RXN11: U1.AC4(PEX_PERN4) ; also on sheet 29
PEX_IPASS_A_RXN12: U1.AA4(PEX_PERN3) ; also on sheet 29
PEX_IPASS_A_RXN13: U1.Y4(PEX_PERN2) ; also on sheet 29
PEX_IPASS_A_RXN14: U1.W4(PEX_PERN1) ; also on sheet 29
PEX_IPASS_A_RXN15: U1.V4(PEX_PERN0) ; also on sheet 29
PEX_IPASS_A_RXP0: U1.AK10(PEX_PERP15) ; also on sheet 29
PEX_IPASS_A_RXP1: U1.AK9(PEX_PERP14) ; also on sheet 29
PEX_IPASS_A_RXP2: U1.AK8(PEX_PERP13) ; also on sheet 29
PEX_IPASS_A_RXP3: U1.AK7(PEX_PERP12) ; also on sheet 29
PEX_IPASS_A_RXP4: U1.AK5(PEX_PERP11) ; also on sheet 29
PEX_IPASS_A_RXP5: U1.AJ5(PEX_PERP10) ; also on sheet 29
PEX_IPASS_A_RXP6: U1.AH5(PEX_PERP9) ; also on sheet 29
PEX_IPASS_A_RXP7: U1.AG5(PEX_PERP8) ; also on sheet 29
PEX_IPASS_A_RXP8: U1.AF5(PEX_PERP7) ; also on sheet 29
PEX_IPASS_A_RXP9: U1.AE5(PEX_PERP6) ; also on sheet 29
PEX_IPASS_A_RXP10: U1.AD5(PEX_PERP5) ; also on sheet 29
PEX_IPASS_A_RXP11: U1.AC5(PEX_PERP4) ; also on sheet 29
PEX_IPASS_A_RXP12: U1.AA5(PEX_PERP3) ; also on sheet 29
PEX_IPASS_A_RXP13: U1.Y5(PEX_PERP2) ; also on sheet 29
PEX_IPASS_A_RXP14: U1.W5(PEX_PERP1) ; also on sheet 29
PEX_IPASS_A_RXP15: U1.V5(PEX_PERP0) ; also on sheet 29
PEX_IPASS_A_TXN0: U1.AP10(PEX_PETN15) ; also on sheet 29
PEX_IPASS_A_TXN1: U1.AP9(PEX_PETN14) ; also on sheet 29
PEX_IPASS_A_TXN2: U1.AP8(PEX_PETN13) ; also on sheet 29
PEX_IPASS_A_TXN3: U1.AP7(PEX_PETN12) ; also on sheet 29
PEX_IPASS_A_TXN4: U1.AK1(PEX_PETN11) ; also on sheet 29
PEX_IPASS_A_TXN5: U1.AJ1(PEX_PETN10) ; also on sheet 29
PEX_IPASS_A_TXN6: U1.AH1(PEX_PETN9) ; also on sheet 29
PEX_IPASS_A_TXN7: U1.AG1(PEX_PETN8) ; also on sheet 29
PEX_IPASS_A_TXN8: U1.AF1(PEX_PETN7) ; also on sheet 29
PEX_IPASS_A_TXN9: U1.AE1(PEX_PETN6) ; also on sheet 29
PEX_IPASS_A_TXN10: U1.AD1(PEX_PETN5) ; also on sheet 29
PEX_IPASS_A_TXN11: U1.AC1(PEX_PETN4) ; also on sheet 29
PEX_IPASS_A_TXN12: U1.AA1(PEX_PETN3) ; also on sheet 29
PEX_IPASS_A_TXN13: U1.Y1(PEX_PETN2) ; also on sheet 29
PEX_IPASS_A_TXN14: U1.W1(PEX_PETN1) ; also on sheet 29
PEX_IPASS_A_TXN15: U1.V1(PEX_PETN0) ; also on sheet 29
PEX_IPASS_A_TXP0: U1.AN10(PEX_PETP15) ; also on sheet 29
PEX_IPASS_A_TXP1: U1.AN9(PEX_PETP14) ; also on sheet 29
PEX_IPASS_A_TXP2: U1.AN8(PEX_PETP13) ; also on sheet 29
PEX_IPASS_A_TXP3: U1.AN7(PEX_PETP12) ; also on sheet 29
PEX_IPASS_A_TXP4: U1.AK2(PEX_PETP11) ; also on sheet 29
PEX_IPASS_A_TXP5: U1.AJ2(PEX_PETP10) ; also on sheet 29
PEX_IPASS_A_TXP6: U1.AH2(PEX_PETP9) ; also on sheet 29
PEX_IPASS_A_TXP7: U1.AG2(PEX_PETP8) ; also on sheet 29
PEX_IPASS_A_TXP8: U1.AF2(PEX_PETP7) ; also on sheet 29
PEX_IPASS_A_TXP9: U1.AE2(PEX_PETP6) ; also on sheet 29
PEX_IPASS_A_TXP10: U1.AD2(PEX_PETP5) ; also on sheet 29
PEX_IPASS_A_TXP11: U1.AC2(PEX_PETP4) ; also on sheet 29
PEX_IPASS_A_TXP12: U1.AA2(PEX_PETP3) ; also on sheet 29
PEX_IPASS_A_TXP13: U1.Y2(PEX_PETP2) ; also on sheet 29
PEX_IPASS_A_TXP14: U1.W2(PEX_PETP1) ; also on sheet 29
PEX_IPASS_A_TXP15: U1.V2(PEX_PETP0) ; also on sheet 29
PEX_NIC1_RXN0: U1.D8(PEX_PERN16) ; also on sheet 39
PEX_NIC1_RXN1: U1.D7(PEX_PERN17) ; also on sheet 39
PEX_NIC1_RXN2: U1.D6(PEX_PERN18) ; also on sheet 39
PEX_NIC1_RXN3: U1.D5(PEX_PERN19) ; also on sheet 39
PEX_NIC1_RXN4: U1.F4(PEX_PERN20) ; also on sheet 39
PEX_NIC1_RXN5: U1.G4(PEX_PERN21) ; also on sheet 39
PEX_NIC1_RXN6: U1.H4(PEX_PERN22) ; also on sheet 39
PEX_NIC1_RXN7: U1.J4(PEX_PERN23) ; also on sheet 39
PEX_NIC1_RXP0: U1.E8(PEX_PERP16) ; also on sheet 39
PEX_NIC1_RXP1: U1.E7(PEX_PERP17) ; also on sheet 39
PEX_NIC1_RXP2: U1.E6(PEX_PERP18) ; also on sheet 39
PEX_NIC1_RXP3: U1.E5(PEX_PERP19) ; also on sheet 39
PEX_NIC1_RXP4: U1.F5(PEX_PERP20) ; also on sheet 39
PEX_NIC1_RXP5: U1.G5(PEX_PERP21) ; also on sheet 39
PEX_NIC1_RXP6: U1.H5(PEX_PERP22) ; also on sheet 39
PEX_NIC1_RXP7: U1.J5(PEX_PERP23) ; also on sheet 39
PEX_NIC1_TXN0: U1.A8(PEX_PETN16) ; also on sheet 39
PEX_NIC1_TXN1: U1.A7(PEX_PETN17) ; also on sheet 39
PEX_NIC1_TXN2: U1.A6(PEX_PETN18) ; also on sheet 39
PEX_NIC1_TXN3: U1.A5(PEX_PETN19) ; also on sheet 39
PEX_NIC1_TXN4: U1.F1(PEX_PETN20) ; also on sheet 39
PEX_NIC1_TXN5: U1.G1(PEX_PETN21) ; also on sheet 39
PEX_NIC1_TXN6: U1.H1(PEX_PETN22) ; also on sheet 39
PEX_NIC1_TXN7: U1.J1(PEX_PETN23) ; also on sheet 39
PEX_NIC1_TXP0: U1.B8(PEX_PETP16) ; also on sheet 39
PEX_NIC1_TXP1: U1.B7(PEX_PETP17) ; also on sheet 39
PEX_NIC1_TXP2: U1.B6(PEX_PETP18) ; also on sheet 39
PEX_NIC1_TXP3: U1.B5(PEX_PETP19) ; also on sheet 39
PEX_NIC1_TXP4: U1.F2(PEX_PETP20) ; also on sheet 39
PEX_NIC1_TXP5: U1.G2(PEX_PETP21) ; also on sheet 39
PEX_NIC1_TXP6: U1.H2(PEX_PETP22) ; also on sheet 39
PEX_NIC1_TXP7: U1.J2(PEX_PETP23) ; also on sheet 39
PEX_NIC2_RXN8: U1.K4(PEX_PERN24) ; also on sheet 39
PEX_NIC2_RXN9: U1.L4(PEX_PERN25) ; also on sheet 39
PEX_NIC2_RXN10: U1.M4(PEX_PERN26) ; also on sheet 39
PEX_NIC2_RXN11: U1.N4(PEX_PERN27) ; also on sheet 39
PEX_NIC2_RXN12: U1.P4(PEX_PERN28) ; also on sheet 39
PEX_NIC2_RXN13: U1.R4(PEX_PERN29) ; also on sheet 39
PEX_NIC2_RXN14: U1.T4(PEX_PERN30) ; also on sheet 39
PEX_NIC2_RXN15: U1.U4(PEX_PERN31) ; also on sheet 39
PEX_NIC2_RXP8: U1.K5(PEX_PERP24) ; also on sheet 39
PEX_NIC2_RXP9: U1.L5(PEX_PERP25) ; also on sheet 39
PEX_NIC2_RXP10: U1.M5(PEX_PERP26) ; also on sheet 39
PEX_NIC2_RXP11: U1.N5(PEX_PERP27) ; also on sheet 39
PEX_NIC2_RXP12: U1.P5(PEX_PERP28) ; also on sheet 39
PEX_NIC2_RXP13: U1.R5(PEX_PERP29) ; also on sheet 39
PEX_NIC2_RXP14: U1.T5(PEX_PERP30) ; also on sheet 39
PEX_NIC2_RXP15: U1.U5(PEX_PERP31) ; also on sheet 39
PEX_NIC2_TXN8: U1.K1(PEX_PETN24) ; also on sheet 39
PEX_NIC2_TXN9: U1.L1(PEX_PETN25) ; also on sheet 39
PEX_NIC2_TXN10: U1.M1(PEX_PETN26) ; also on sheet 39
PEX_NIC2_TXN11: U1.N1(PEX_PETN27) ; also on sheet 39
PEX_NIC2_TXN12: U1.P1(PEX_PETN28) ; also on sheet 39
PEX_NIC2_TXN13: U1.R1(PEX_PETN29) ; also on sheet 39
PEX_NIC2_TXN14: U1.T1(PEX_PETN30) ; also on sheet 39
PEX_NIC2_TXN15: U1.U1(PEX_PETN31) ; also on sheet 39
PEX_NIC2_TXP8: U1.K2(PEX_PETP24) ; also on sheet 39
PEX_NIC2_TXP9: U1.L2(PEX_PETP25) ; also on sheet 39
PEX_NIC2_TXP10: U1.M2(PEX_PETP26) ; also on sheet 39
PEX_NIC2_TXP11: U1.N2(PEX_PETP27) ; also on sheet 39
PEX_NIC2_TXP12: U1.P2(PEX_PETP28) ; also on sheet 39
PEX_NIC2_TXP13: U1.R2(PEX_PETP29) ; also on sheet 39
PEX_NIC2_TXP14: U1.T2(PEX_PETP30) ; also on sheet 39
PEX_NIC2_TXP15: U1.U2(PEX_PETP31) ; also on sheet 39
PEX_PE0_RXN0: U1.AL26(PEX_PERN47) ; also on sheet 31
PEX_PE0_RXN1: U1.AL25(PEX_PERN46) ; also on sheet 31
PEX_PE0_RXN2: U1.AL24(PEX_PERN45) ; also on sheet 31
PEX_PE0_RXN3: U1.AL23(PEX_PERN44) ; also on sheet 31
PEX_PE0_RXN4: U1.AL22(PEX_PERN43) ; also on sheet 31
PEX_PE0_RXN5: U1.AL21(PEX_PERN42) ; also on sheet 31
PEX_PE0_RXN6: U1.AL20(PEX_PERN41) ; also on sheet 31
PEX_PE0_RXN7: U1.AL19(PEX_PERN40) ; also on sheet 31
PEX_PE0_RXN8: U1.AL18(PEX_PERN39) ; also on sheet 31
PEX_PE0_RXN9: U1.AL17(PEX_PERN38) ; also on sheet 31
PEX_PE0_RXN10: U1.AL16(PEX_PERN37) ; also on sheet 31
PEX_PE0_RXN11: U1.AL15(PEX_PERN36) ; also on sheet 31
PEX_PE0_RXN12: U1.AL14(PEX_PERN35) ; also on sheet 31
PEX_PE0_RXN13: U1.AL13(PEX_PERN34) ; also on sheet 31
PEX_PE0_RXN14: U1.AL12(PEX_PERN33) ; also on sheet 31
PEX_PE0_RXN15: U1.AL11(PEX_PERN32) ; also on sheet 31
PEX_PE0_RXP0: U1.AK26(PEX_PERP47) ; also on sheet 31
PEX_PE0_RXP1: U1.AK25(PEX_PERP46) ; also on sheet 31
PEX_PE0_RXP2: U1.AK24(PEX_PERP45) ; also on sheet 31
PEX_PE0_RXP3: U1.AK23(PEX_PERP44) ; also on sheet 31
PEX_PE0_RXP4: U1.AK22(PEX_PERP43) ; also on sheet 31
PEX_PE0_RXP5: U1.AK21(PEX_PERP42) ; also on sheet 31
PEX_PE0_RXP6: U1.AK20(PEX_PERP41) ; also on sheet 31
PEX_PE0_RXP7: U1.AK19(PEX_PERP40) ; also on sheet 31
PEX_PE0_RXP8: U1.AK18(PEX_PERP39) ; also on sheet 31
PEX_PE0_RXP9: U1.AK17(PEX_PERP38) ; also on sheet 31
PEX_PE0_RXP10: U1.AK16(PEX_PERP37) ; also on sheet 31
PEX_PE0_RXP11: U1.AK15(PEX_PERP36) ; also on sheet 31
PEX_PE0_RXP12: U1.AK14(PEX_PERP35) ; also on sheet 31
PEX_PE0_RXP13: U1.AK13(PEX_PERP34) ; also on sheet 31
PEX_PE0_RXP14: U1.AK12(PEX_PERP33) ; also on sheet 31
PEX_PE0_RXP15: U1.AK11(PEX_PERP32) ; also on sheet 31
PEX_PE0_TXN0: U1.AP26(PEX_PETN47) ; also on sheet 31
PEX_PE0_TXN1: U1.AP25(PEX_PETN46) ; also on sheet 31
PEX_PE0_TXN2: U1.AP24(PEX_PETN45) ; also on sheet 31
PEX_PE0_TXN3: U1.AP23(PEX_PETN44) ; also on sheet 31
PEX_PE0_TXN4: U1.AP22(PEX_PETN43) ; also on sheet 31
PEX_PE0_TXN5: U1.AP21(PEX_PETN42) ; also on sheet 31
PEX_PE0_TXN6: U1.AP20(PEX_PETN41) ; also on sheet 31
PEX_PE0_TXN7: U1.AP19(PEX_PETN40) ; also on sheet 31
PEX_PE0_TXN8: U1.AP18(PEX_PETN39) ; also on sheet 31
PEX_PE0_TXN9: U1.AP17(PEX_PETN38) ; also on sheet 31
PEX_PE0_TXN10: U1.AP16(PEX_PETN37) ; also on sheet 31
PEX_PE0_TXN11: U1.AP15(PEX_PETN36) ; also on sheet 31
PEX_PE0_TXN12: U1.AP14(PEX_PETN35) ; also on sheet 31
PEX_PE0_TXN13: U1.AP13(PEX_PETN34) ; also on sheet 31
PEX_PE0_TXN14: U1.AP12(PEX_PETN33) ; also on sheet 31
PEX_PE0_TXN15: U1.AP11(PEX_PETN32) ; also on sheet 31
PEX_PE0_TXP0: U1.AN26(PEX_PETP47) ; also on sheet 31
PEX_PE0_TXP1: U1.AN25(PEX_PETP46) ; also on sheet 31
PEX_PE0_TXP2: U1.AN24(PEX_PETP45) ; also on sheet 31
PEX_PE0_TXP3: U1.AN23(PEX_PETP44) ; also on sheet 31
PEX_PE0_TXP4: U1.AN22(PEX_PETP43) ; also on sheet 31
PEX_PE0_TXP5: U1.AN21(PEX_PETP42) ; also on sheet 31
PEX_PE0_TXP6: U1.AN20(PEX_PETP41) ; also on sheet 31
PEX_PE0_TXP7: U1.AN19(PEX_PETP40) ; also on sheet 31
PEX_PE0_TXP8: U1.AN18(PEX_PETP39) ; also on sheet 31
PEX_PE0_TXP9: U1.AN17(PEX_PETP38) ; also on sheet 31
PEX_PE0_TXP10: U1.AN16(PEX_PETP37) ; also on sheet 31
PEX_PE0_TXP11: U1.AN15(PEX_PETP36) ; also on sheet 31
PEX_PE0_TXP12: U1.AN14(PEX_PETP35) ; also on sheet 31
PEX_PE0_TXP13: U1.AN13(PEX_PETP34) ; also on sheet 31
PEX_PE0_TXP14: U1.AN12(PEX_PETP33) ; also on sheet 31
PEX_PE0_TXP15: U1.AN11(PEX_PETP32) ; also on sheet 31
PEX_PE1_RXN0: U1.V31(PEX_PERN79) ; also on sheet 32
PEX_PE1_RXN1: U1.W31(PEX_PERN78) ; also on sheet 32
PEX_PE1_RXN2: U1.Y31(PEX_PERN77) ; also on sheet 32
PEX_PE1_RXN3: U1.AA31(PEX_PERN76) ; also on sheet 32
PEX_PE1_RXN4: U1.AB31(PEX_PERN75) ; also on sheet 32
PEX_PE1_RXN5: U1.AC31(PEX_PERN74) ; also on sheet 32
PEX_PE1_RXN6: U1.AD31(PEX_PERN73) ; also on sheet 32
PEX_PE1_RXN7: U1.AE31(PEX_PERN72) ; also on sheet 32
PEX_PE1_RXN8: U1.AF31(PEX_PERN71) ; also on sheet 32
PEX_PE1_RXN9: U1.AG31(PEX_PERN70) ; also on sheet 32
PEX_PE1_RXN10: U1.AH31(PEX_PERN69) ; also on sheet 32
PEX_PE1_RXN11: U1.AJ31(PEX_PERN68) ; also on sheet 32
PEX_PE1_RXN12: U1.AL30(PEX_PERN67) ; also on sheet 32
PEX_PE1_RXN13: U1.AL29(PEX_PERN66) ; also on sheet 32
PEX_PE1_RXN14: U1.AL28(PEX_PERN65) ; also on sheet 32
PEX_PE1_RXN15: U1.AL27(PEX_PERN64) ; also on sheet 32
PEX_PE1_RXP0: U1.V30(PEX_PERP79) ; also on sheet 32
PEX_PE1_RXP1: U1.W30(PEX_PERP78) ; also on sheet 32
PEX_PE1_RXP2: U1.Y30(PEX_PERP77) ; also on sheet 32
PEX_PE1_RXP3: U1.AA30(PEX_PERP76) ; also on sheet 32
PEX_PE1_RXP4: U1.AB30(PEX_PERP75) ; also on sheet 32
PEX_PE1_RXP5: U1.AC30(PEX_PERP74) ; also on sheet 32
PEX_PE1_RXP6: U1.AD30(PEX_PERP73) ; also on sheet 32
PEX_PE1_RXP7: U1.AE30(PEX_PERP72) ; also on sheet 32
PEX_PE1_RXP8: U1.AF30(PEX_PERP71) ; also on sheet 32
PEX_PE1_RXP9: U1.AG30(PEX_PERP70) ; also on sheet 32
PEX_PE1_RXP10: U1.AH30(PEX_PERP69) ; also on sheet 32
PEX_PE1_RXP11: U1.AJ30(PEX_PERP68) ; also on sheet 32
PEX_PE1_RXP12: U1.AK30(PEX_PERP67) ; also on sheet 32
PEX_PE1_RXP13: U1.AK29(PEX_PERP66) ; also on sheet 32
PEX_PE1_RXP14: U1.AK28(PEX_PERP65) ; also on sheet 32
PEX_PE1_RXP15: U1.AK27(PEX_PERP64) ; also on sheet 32
PEX_PE1_TXN0: U1.V34(PEX_PETN79) ; also on sheet 32
PEX_PE1_TXN1: U1.W34(PEX_PETN78) ; also on sheet 32
PEX_PE1_TXN2: U1.Y34(PEX_PETN77) ; also on sheet 32
PEX_PE1_TXN3: U1.AA34(PEX_PETN76) ; also on sheet 32
PEX_PE1_TXN4: U1.AB34(PEX_PETN75) ; also on sheet 32
PEX_PE1_TXN5: U1.AC34(PEX_PETN74) ; also on sheet 32
PEX_PE1_TXN6: U1.AD34(PEX_PETN73) ; also on sheet 32
PEX_PE1_TXN7: U1.AE34(PEX_PETN72) ; also on sheet 32
PEX_PE1_TXN8: U1.AF34(PEX_PETN71) ; also on sheet 32
PEX_PE1_TXN9: U1.AG34(PEX_PETN70) ; also on sheet 32
PEX_PE1_TXN10: U1.AH34(PEX_PETN69) ; also on sheet 32
PEX_PE1_TXN11: U1.AJ34(PEX_PETN68) ; also on sheet 32
PEX_PE1_TXN12: U1.AP30(PEX_PETN67) ; also on sheet 32
PEX_PE1_TXN13: U1.AP29(PEX_PETN66) ; also on sheet 32
PEX_PE1_TXN14: U1.AP28(PEX_PETN65) ; also on sheet 32
PEX_PE1_TXN15: U1.AP27(PEX_PETN64) ; also on sheet 32
PEX_PE1_TXP0: U1.V33(PEX_PETP79) ; also on sheet 32
PEX_PE1_TXP1: U1.W33(PEX_PETP78) ; also on sheet 32
PEX_PE1_TXP2: U1.Y33(PEX_PETP77) ; also on sheet 32
PEX_PE1_TXP3: U1.AA33(PEX_PETP76) ; also on sheet 32
PEX_PE1_TXP4: U1.AB33(PEX_PETP75) ; also on sheet 32
PEX_PE1_TXP5: U1.AC33(PEX_PETP74) ; also on sheet 32
PEX_PE1_TXP6: U1.AD33(PEX_PETP73) ; also on sheet 32
PEX_PE1_TXP7: U1.AE33(PEX_PETP72) ; also on sheet 32
PEX_PE1_TXP8: U1.AF33(PEX_PETP71) ; also on sheet 32
PEX_PE1_TXP9: U1.AG33(PEX_PETP70) ; also on sheet 32
PEX_PE1_TXP10: U1.AH33(PEX_PETP69) ; also on sheet 32
PEX_PE1_TXP11: U1.AJ33(PEX_PETP68) ; also on sheet 32
PEX_PE1_TXP12: U1.AN30(PEX_PETP67) ; also on sheet 32
PEX_PE1_TXP13: U1.AN29(PEX_PETP66) ; also on sheet 32
PEX_PE1_TXP14: U1.AN28(PEX_PETP65) ; also on sheet 32
PEX_PE1_TXP15: U1.AN27(PEX_PETP64) ; also on sheet 32
PEX_PE2_RXN0: U1.D25(PEX_PERN95) ; also on sheet 33
PEX_PE2_RXN1: U1.D26(PEX_PERN94) ; also on sheet 33
PEX_PE2_RXN2: U1.D27(PEX_PERN93) ; also on sheet 33
PEX_PE2_RXN3: U1.D28(PEX_PERN92) ; also on sheet 33
PEX_PE2_RXN4: U1.E31(PEX_PERN91) ; also on sheet 33
PEX_PE2_RXN5: U1.F31(PEX_PERN90) ; also on sheet 33
PEX_PE2_RXN6: U1.G31(PEX_PERN89) ; also on sheet 33
PEX_PE2_RXN7: U1.H31(PEX_PERN88) ; also on sheet 33
PEX_PE2_RXN8: U1.J31(PEX_PERN87) ; also on sheet 33
PEX_PE2_RXN9: U1.K31(PEX_PERN86) ; also on sheet 33
PEX_PE2_RXN10: U1.L31(PEX_PERN85) ; also on sheet 33
PEX_PE2_RXN11: U1.M31(PEX_PERN84) ; also on sheet 33
PEX_PE2_RXN12: U1.P31(PEX_PERN83) ; also on sheet 33
PEX_PE2_RXN13: U1.R31(PEX_PERN82) ; also on sheet 33
PEX_PE2_RXN14: U1.T31(PEX_PERN81) ; also on sheet 33
PEX_PE2_RXN15: U1.U31(PEX_PERN80) ; also on sheet 33
PEX_PE2_RXP0: U1.E25(PEX_PERP95) ; also on sheet 33
PEX_PE2_RXP1: U1.E26(PEX_PERP94) ; also on sheet 33
PEX_PE2_RXP2: U1.E27(PEX_PERP93) ; also on sheet 33
PEX_PE2_RXP3: U1.E28(PEX_PERP92) ; also on sheet 33
PEX_PE2_RXP4: U1.E30(PEX_PERP91) ; also on sheet 33
PEX_PE2_RXP5: U1.F30(PEX_PERP90) ; also on sheet 33
PEX_PE2_RXP6: U1.G30(PEX_PERP89) ; also on sheet 33
PEX_PE2_RXP7: U1.H30(PEX_PERP88) ; also on sheet 33
PEX_PE2_RXP8: U1.J30(PEX_PERP87) ; also on sheet 33
PEX_PE2_RXP9: U1.K30(PEX_PERP86) ; also on sheet 33
PEX_PE2_RXP10: U1.L30(PEX_PERP85) ; also on sheet 33
PEX_PE2_RXP11: U1.M30(PEX_PERP84) ; also on sheet 33
PEX_PE2_RXP12: U1.P30(PEX_PERP83) ; also on sheet 33
PEX_PE2_RXP13: U1.R30(PEX_PERP82) ; also on sheet 33
PEX_PE2_RXP14: U1.T30(PEX_PERP81) ; also on sheet 33
PEX_PE2_RXP15: U1.U30(PEX_PERP80) ; also on sheet 33
PEX_PE2_TXN0: U1.A25(PEX_PETN95) ; also on sheet 33
PEX_PE2_TXN1: U1.A26(PEX_PETN94) ; also on sheet 33
PEX_PE2_TXN2: U1.A27(PEX_PETN93) ; also on sheet 33
PEX_PE2_TXN3: U1.A28(PEX_PETN92) ; also on sheet 33
PEX_PE2_TXN4: U1.E34(PEX_PETN91) ; also on sheet 33
PEX_PE2_TXN5: U1.F34(PEX_PETN90) ; also on sheet 33
PEX_PE2_TXN6: U1.G34(PEX_PETN89) ; also on sheet 33
PEX_PE2_TXN7: U1.H34(PEX_PETN88) ; also on sheet 33
PEX_PE2_TXN8: U1.J34(PEX_PETN87) ; also on sheet 33
PEX_PE2_TXN9: U1.K34(PEX_PETN86) ; also on sheet 33
PEX_PE2_TXN10: U1.L34(PEX_PETN85) ; also on sheet 33
PEX_PE2_TXN11: U1.M34(PEX_PETN84) ; also on sheet 33
PEX_PE2_TXN12: U1.P34(PEX_PETN83) ; also on sheet 33
PEX_PE2_TXN13: U1.R34(PEX_PETN82) ; also on sheet 33
PEX_PE2_TXN14: U1.T34(PEX_PETN81) ; also on sheet 33
PEX_PE2_TXN15: U1.U34(PEX_PETN80) ; also on sheet 33
PEX_PE2_TXP0: U1.B25(PEX_PETP95) ; also on sheet 33
PEX_PE2_TXP1: U1.B26(PEX_PETP94) ; also on sheet 33
PEX_PE2_TXP2: U1.B27(PEX_PETP93) ; also on sheet 33
PEX_PE2_TXP3: U1.B28(PEX_PETP92) ; also on sheet 33
PEX_PE2_TXP4: U1.E33(PEX_PETP91) ; also on sheet 33
PEX_PE2_TXP5: U1.F33(PEX_PETP90) ; also on sheet 33
PEX_PE2_TXP6: U1.G33(PEX_PETP89) ; also on sheet 33
PEX_PE2_TXP7: U1.H33(PEX_PETP88) ; also on sheet 33
PEX_PE2_TXP8: U1.J33(PEX_PETP87) ; also on sheet 33
PEX_PE2_TXP9: U1.K33(PEX_PETP86) ; also on sheet 33
PEX_PE2_TXP10: U1.L33(PEX_PETP85) ; also on sheet 33
PEX_PE2_TXP11: U1.M33(PEX_PETP84) ; also on sheet 33
PEX_PE2_TXP12: U1.P33(PEX_PETP83) ; also on sheet 33
PEX_PE2_TXP13: U1.R33(PEX_PETP82) ; also on sheet 33
PEX_PE2_TXP14: U1.T33(PEX_PETP81) ; also on sheet 33
PEX_PE2_TXP15: U1.U33(PEX_PETP80) ; also on sheet 33
PEX_PE3_RXN0: U1.D9(PEX_PERN63) ; also on sheet 34
PEX_PE3_RXN1: U1.D10(PEX_PERN62) ; also on sheet 34
PEX_PE3_RXN2: U1.D11(PEX_PERN61) ; also on sheet 34
PEX_PE3_RXN3: U1.D12(PEX_PERN60) ; also on sheet 34
PEX_PE3_RXN4: U1.D13(PEX_PERN59) ; also on sheet 34
PEX_PE3_RXN5: U1.D14(PEX_PERN58) ; also on sheet 34
PEX_PE3_RXN6: U1.D15(PEX_PERN57) ; also on sheet 34
PEX_PE3_RXN7: U1.D16(PEX_PERN56) ; also on sheet 34
PEX_PE3_RXN8: U1.D17(PEX_PERN55) ; also on sheet 34
PEX_PE3_RXN9: U1.D18(PEX_PERN54) ; also on sheet 34
PEX_PE3_RXN10: U1.D19(PEX_PERN53) ; also on sheet 34
PEX_PE3_RXN11: U1.D20(PEX_PERN52) ; also on sheet 34
PEX_PE3_RXN12: U1.D21(PEX_PERN51) ; also on sheet 34
PEX_PE3_RXN13: U1.D22(PEX_PERN50) ; also on sheet 34
PEX_PE3_RXN14: U1.D23(PEX_PERN49) ; also on sheet 34
PEX_PE3_RXN15: U1.D24(PEX_PERN48) ; also on sheet 34
PEX_PE3_RXP0: U1.E9(PEX_PERP63) ; also on sheet 34
PEX_PE3_RXP1: U1.E10(PEX_PERP62) ; also on sheet 34
PEX_PE3_RXP2: U1.E11(PEX_PERP61) ; also on sheet 34
PEX_PE3_RXP3: U1.E12(PEX_PERP60) ; also on sheet 34
PEX_PE3_RXP4: U1.E13(PEX_PERP59) ; also on sheet 34
PEX_PE3_RXP5: U1.E14(PEX_PERP58) ; also on sheet 34
PEX_PE3_RXP6: U1.E15(PEX_PERP57) ; also on sheet 34
PEX_PE3_RXP7: U1.E16(PEX_PERP56) ; also on sheet 34
PEX_PE3_RXP8: U1.E17(PEX_PERP55) ; also on sheet 34
PEX_PE3_RXP9: U1.E18(PEX_PERP54) ; also on sheet 34
PEX_PE3_RXP10: U1.E19(PEX_PERP53) ; also on sheet 34
PEX_PE3_RXP11: U1.E20(PEX_PERP52) ; also on sheet 34
PEX_PE3_RXP12: U1.E21(PEX_PERP51) ; also on sheet 34
PEX_PE3_RXP13: U1.E22(PEX_PERP50) ; also on sheet 34
PEX_PE3_RXP14: U1.E23(PEX_PERP49) ; also on sheet 34
PEX_PE3_RXP15: U1.E24(PEX_PERP48) ; also on sheet 34
PEX_PE3_TXN0: U1.A9(PEX_PETN63) ; also on sheet 34
PEX_PE3_TXN1: U1.A10(PEX_PETN62) ; also on sheet 34
PEX_PE3_TXN2: U1.A11(PEX_PETN61) ; also on sheet 34
PEX_PE3_TXN3: U1.A12(PEX_PETN60) ; also on sheet 34
PEX_PE3_TXN4: U1.A13(PEX_PETN59) ; also on sheet 34
PEX_PE3_TXN5: U1.A14(PEX_PETN58) ; also on sheet 34
PEX_PE3_TXN6: U1.A15(PEX_PETN57) ; also on sheet 34
PEX_PE3_TXN7: U1.A16(PEX_PETN56) ; also on sheet 34
PEX_PE3_TXN8: U1.A17(PEX_PETN55) ; also on sheet 34
PEX_PE3_TXN9: U1.A18(PEX_PETN54) ; also on sheet 34
PEX_PE3_TXN10: U1.A19(PEX_PETN53) ; also on sheet 34
PEX_PE3_TXN11: U1.A20(PEX_PETN52) ; also on sheet 34
PEX_PE3_TXN12: U1.A21(PEX_PETN51) ; also on sheet 34
PEX_PE3_TXN13: U1.A22(PEX_PETN50) ; also on sheet 34
PEX_PE3_TXN14: U1.A23(PEX_PETN49) ; also on sheet 34
PEX_PE3_TXN15: U1.A24(PEX_PETN48) ; also on sheet 34
PEX_PE3_TXP0: U1.B9(PEX_PETP63) ; also on sheet 34
PEX_PE3_TXP1: U1.B10(PEX_PETP62) ; also on sheet 34
PEX_PE3_TXP2: U1.B11(PEX_PETP61) ; also on sheet 34
PEX_PE3_TXP3: U1.B12(PEX_PETP60) ; also on sheet 34
PEX_PE3_TXP4: U1.B13(PEX_PETP59) ; also on sheet 34
PEX_PE3_TXP5: U1.B14(PEX_PETP58) ; also on sheet 34
PEX_PE3_TXP6: U1.B15(PEX_PETP57) ; also on sheet 34
PEX_PE3_TXP7: U1.B16(PEX_PETP56) ; also on sheet 34
PEX_PE3_TXP8: U1.B17(PEX_PETP55) ; also on sheet 34
PEX_PE3_TXP9: U1.B18(PEX_PETP54) ; also on sheet 34
PEX_PE3_TXP10: U1.B19(PEX_PETP53) ; also on sheet 34
PEX_PE3_TXP11: U1.B20(PEX_PETP52) ; also on sheet 34
PEX_PE3_TXP12: U1.B21(PEX_PETP51) ; also on sheet 34
PEX_PE3_TXP13: U1.B22(PEX_PETP50) ; also on sheet 34
PEX_PE3_TXP14: U1.B23(PEX_PETP49) ; also on sheet 34
PEX_PE3_TXP15: U1.B24(PEX_PETP48) ; also on sheet 34
PLX1_JTAG_TCK: R63.2 U1.AB7(JTAG_TCK)
PLX1_JTAG_TDI: R60.2 U1.D1(JTAG_TDI)
PLX1_JTAG_TMS: R61.2 U1.N8(JTAG_TMS)
PLX1_PORT_GOOD0_N_R: D1.1 R76.2
PLX1_PORT_GOOD4_N_R: D21.1 R1166.2
PLX1_PORT_GOOD5_N_R: D23.1 R1173.2
PLX1_PORT_GOOD8_N_R: D2.1 R83.2
PLX1_PORT_GOOD12_N_R: D3.1 R85.2
PLX1_PORT_GOOD16_N_R: D4.1 R87.2
PLX1_PORT_GOOD20_N_R: D5.1 R89.2
PLX1_REXT_A0: R1.2 U1.W6(REXT_A0)
PLX1_REXT_A1: R9.2 U1.AE6(REXT_A1)
PLX1_REXT_A2: R4.2 U1.AH6(REXT_A2)
PLX1_REXT_A3: R6.2 U1.AJ9(REXT_A3)
PLX1_REXT_A4: R10.2 U1.F9(REXT_A4)
PLX1_REXT_A5: R12.2 U1.H6(REXT_A5)
PLX1_REXT_A6: R16.2 U1.L6(REXT_A6)
PLX1_REXT_A7: R13.2 U1.T6(REXT_A7)
PLX1_REXT_A8: R19.2 U1.AJ11(REXT_A8)
PLX1_REXT_A9: R21.2 U1.AJ17(REXT_A9)
PLX1_REXT_A10: R23.2 U1.AJ21(REXT_A10)
PLX1_REXT_A11: R25.2 U1.AJ24(REXT_A11)
PLX1_REXT_A12: R28.2 U1.F25(REXT_A12)
PLX1_REXT_A13: R29.2 U1.F19(REXT_A13)
PLX1_REXT_A14: R30.2 U1.F14(REXT_A14)
PLX1_REXT_A15: R32.2 U1.F11(REXT_A15)
PLX1_REXT_A16: R37.2 U1.AJ27(REXT_A16)
PLX1_REXT_A17: R39.2 U1.AG29(REXT_A17)
PLX1_REXT_A18: R43.2 U1.AB29(REXT_A18)
PLX1_REXT_A19: R40.2 U1.Y29(REXT_A19)
PLX1_REXT_A20: R46.2 U1.U29(REXT_A20)
PLX1_REXT_A21: R48.2 U1.M29(REXT_A21)
PLX1_REXT_A22: R50.2 U1.H29(REXT_A22)
PLX1_REXT_A23: R52.2 U1.F27(REXT_A23)
PLX1_REXT_B0: R2.2 U1.V6(REXT_B0)
PLX1_REXT_B1: R3.2 U1.AD6(REXT_B1)
PLX1_REXT_B2: R5.2 U1.AG6(REXT_B2)
PLX1_REXT_B3: R7.2 U1.AJ8(REXT_B3)
PLX1_REXT_B4: R11.2 U1.F8(REXT_B4)
PLX1_REXT_B5: R15.2 U1.J6(REXT_B5)
PLX1_REXT_B6: R17.2 U1.M6(REXT_B6)
PLX1_REXT_B7: R14.2 U1.R6(REXT_B7)
PLX1_REXT_B8: R20.2 U1.AJ10(REXT_B8)
PLX1_REXT_B9: R22.2 U1.AJ16(REXT_B9)
PLX1_REXT_B10: R24.2 U1.AJ20(REXT_B10)
PLX1_REXT_B11: R26.2 U1.AJ23(REXT_B11)
PLX1_REXT_B12: R34.2 U1.F24(REXT_B12)
PLX1_REXT_B13: R35.2 U1.F18(REXT_B13)
PLX1_REXT_B14: R31.2 U1.F13(REXT_B14)
PLX1_REXT_B15: R36.2 U1.F10(REXT_B15)
PLX1_REXT_B16: R38.2 U1.AJ26(REXT_B16)
PLX1_REXT_B17: R42.2 U1.AF29(REXT_B17)
PLX1_REXT_B18: R44.2 U1.AA29(REXT_B18)
PLX1_REXT_B19: R41.2 U1.W29(REXT_B19)
PLX1_REXT_B20: R47.2 U1.T29(REXT_B20)
PLX1_REXT_B21: R49.2 U1.L29(REXT_B21)
PLX1_REXT_B22: R51.2 U1.G29(REXT_B22)
PLX1_REXT_B23: R53.2 U1.F26(REXT_B23)
PLX1_REXT_CMU0: R8.2 U1.AF6(REXT_CMU0)
PLX1_REXT_CMU1: R18.2 U1.K6(REXT_CMU1)
PLX1_REXT_CMU2: R27.2 U1.AJ18(REXT_CMU2)
PLX1_REXT_CMU3: R33.2 U1.F16(REXT_CMU3)
PLX1_REXT_CMU4: R45.2 U1.AE29(REXT_CMU4)
PLX1_REXT_CMU5: R54.2 U1.J29(REXT_CMU5)
PLX1_THERMAL_SENSE0: R70.1 U1.B30(VDD18A_THERMAL_SENSE0)
PLX1_THERMAL_SENSE1: R71.1 U1.AN32(VDD18A_THERMAL_SENSE1)
PLX_I2C_ADDR: R74.1 R75.2 U1.K11(I2C_ADDR)
PLX_JTAG_TRST_N: R58.2 U1.P7(JTAG_TRST#)
PLX_PORT_GOOD0_D_N: D1.2 Q1.3(D)
PLX_PORT_GOOD0_G_N: Q1.1(G) Q2.3(D) R77.2
PLX_PORT_GOOD0_N: Q2.1(G) U1.G13(PORT_GOOD0#_SHP_PERST0#_HP_PWREN_A)
PLX_PORT_GOOD4_D_N: D21.2 Q45.3(D)
PLX_PORT_GOOD4_G_N: Q44.3(D) Q45.1(G) R1167.2
PLX_PORT_GOOD4_N: Q44.1(G) U1.C3(PORT_GOOD4#_SHP_PERST4#_HP_PWREN_B)
PLX_PORT_GOOD5_D_N: D23.2 Q49.3(D)
PLX_PORT_GOOD5_G_N: Q48.3(D) Q49.1(G) R1174.2
PLX_PORT_GOOD5_N: Q48.1(G) U1.K9(PORT_GOOD5#_SHP_PERST5#_HP_CLKEN_B#)
PLX_PORT_GOOD8_D_N: D2.2 Q3.3(D)
PLX_PORT_GOOD8_G_N: Q3.1(G) Q4.3(D) R84.2
PLX_PORT_GOOD8_N: Q4.1(G) U1.AF24(PORT_GOOD8#_SHP_PERST8#_HP_PWREN_C)
PLX_PORT_GOOD12_D_N: D3.2 Q5.3(D)
PLX_PORT_GOOD12_G_N: Q5.1(G) Q6.3(D) R86.2
PLX_PORT_GOOD12_N: Q6.1(G) U1.G23(PORT_GOOD12#_SHP_PERST12#_HP_PWREN_D)
PLX_PORT_GOOD16_D_N: D4.2 Q7.3(D)
PLX_PORT_GOOD16_G_N: Q7.1(G) Q8.3(D) R88.2
PLX_PORT_GOOD16_N: Q8.1(G) U1.AC28(PORT_GOOD16#_SHP_PERST16#_HP_PWREN_E)
PLX_PORT_GOOD20_D_N: D5.2 Q9.3(D)
PLX_PORT_GOOD20_G_N: Q9.1(G) Q10.3(D) R90.2
PLX_PORT_GOOD20_N: Q10.1(G) U1.M26(PORT_GOOD20#_SHP_PERST20#_HP_PWREN_F)
PLX_SPARE0: R69.1 U1.H15(SPARE0)
PLX_SPARE1: R72.2 U1.J18(SPARE1)
PLX_SPARE2: R73.2 U1.AE19(SPARE2)
RST_PLX_N: R56.1 ; also on sheet 55
RST_PLX_PERST_N: R55.1 R56.2 U1.AG10(PEX_PERST#)
SMB_PLX1_SCL: R66.2 ; also on sheet 46
SMB_PLX1_SCL_R: R62.2 R66.1 U1.R8(I2C_SCL0)
SMB_PLX1_SDA: R65.2 ; also on sheet 46
SMB_PLX1_SDA_R: R57.2 R65.1 U1.R7(I2C_SDA0)
SPI_PLX_CS_N: R59.1 R78.2 U2.1(S#)
SPI_PLX_CS_N_R: R59.2 U1.AG14(EE_CS#)
SPI_PLX_DI: R67.1 U2.5(D)
SPI_PLX_DI_R: R67.2 U1.J11(EE_DI)
SPI_PLX_DO: R68.1 R79.2 U2.2(Q)
SPI_PLX_DO_R: R68.2 U1.AA8(EE_DO)
SPI_PLX_HOLD_N: R81.2 U2.7(HOLD#)
SPI_PLX_SK: R64.1 U2.6(C)
SPI_PLX_SK_R: R64.2 U1.AM5(EE_SK)
SPI_PLX_WP_N: R80.2 R82.1 U2.3(W#)
TP_PLX1_PORT_GOOD1_N: U1.AH15(PORT_GOOD1#_SHP_PERST1#_HP_CLKEN_A#)
TP_PLX1_PORT_GOOD2_N: U1.AG16(PORT_GOOD2#_SHP_PERST2#_HP_PERST_A#)
TP_PLX1_PORT_GOOD3_N: U1.AG13(PORT_GOOD3#_SHP_PERST3#_HP_PWRLED_A#)
TP_PLX1_PORT_GOOD6_N: U1.D3(PORT_GOOD6#_SHP_PERST6#_HP_PERST_B#)
TP_PLX1_PORT_GOOD7_N: U1.H9(PORT_GOOD7#_SHP_PERST7#_HP_PWRLED_B#)
TP_PLX1_PORT_GOOD10_N: U1.AF25(PORT_GOOD10#_SHP_PERST10#_HP_PERST_C#)
TP_PLX1_PORT_GOOD11_N: U1.AH23(PORT_GOOD11#_SHP_PERST11#_HP_PWRLED_C#)
TP_PLX1_PORT_GOOD14_N: U1.H19(PORT_GOOD14#_SHP_PERST14#_HP_PERST_D#)
TP_PLX1_PORT_GOOD15_N: U1.H23(PORT_GOOD15#_SHP_PERST15#_HP_PWRLED_D#)
TP_PLX1_PORT_GOOD18_N: U1.AN34(PORT_GOOD18#_SHP_PERST18#_HP_PERST_E#)
TP_PLX1_PORT_GOOD19_N: U1.AD28(PORT_GOOD19#_SHP_PERST19#_HP_PWRLED_E#)
TP_PLX1_PORT_GOOD22_N: U1.C30(PORT_GOOD22#_SHP_PERST22#_HP_PERST_F#)
TP_PLX1_PORT_GOOD23_N: U1.C34(PORT_GOOD23#_SHP_PERST23#_HP_PWRLED_F#)
TP_PLX1_REFCLK_SSC_N8: U1.AH11(PEX_REFCLK_SSCN8)
TP_PLX1_REFCLK_SSC_N9: U1.AH17(PEX_REFCLK_SSCN9)
TP_PLX1_REFCLK_SSC_N10: U1.AH21(PEX_REFCLK_SSCN10)
TP_PLX1_REFCLK_SSC_N11: U1.AH24(PEX_REFCLK_SSCN11)
TP_PLX1_REFCLK_SSC_P8: U1.AG11(PEX_REFCLK_SSCP8)
TP_PLX1_REFCLK_SSC_P9: U1.AG17(PEX_REFCLK_SSCP9)
TP_PLX1_REFCLK_SSC_P10: U1.AG21(PEX_REFCLK_SSCP10)
TP_PLX1_REFCLK_SSC_P11: U1.AG24(PEX_REFCLK_SSCP11)
TP_PLX1_VS0_FATAL_ERR_N: U1.U8(VS0_FATAL_ERR#)
TP_PLX1_VS0_PEX_INTA_N: U1.J14(VS0_PEX_INTA#)
TP_PLX1_VS1_FATAL_ERR_N: U1.J17(VS1_FATAL_ERR#)
TP_PLX1_VS1_PEX_INTA_N: U1.B1(VS1_PEX_INTA#)
TP_PLX1_VS2_FATAL_ERR_N: U1.AE20(VS2_FATAL_ERR#)
TP_PLX1_VS2_PEX_INTA_N: U1.AG25(VS2_PEX_INTA#)
TP_PLX1_VS3_FATAL_ERR_N: U1.A31(VS3_FATAL_ERR#)
TP_PLX1_VS3_PEX_INTA_N: U1.G24(VS3_PEX_INTA#)
TP_PLX_GPIO0: U1.AH14(GPIO0_HP_MRL_A#)
TP_PLX_GPIO1: U1.AF8(GPIO1_HP_PWRFLT_A#)
TP_PLX_GPIO2: U1.AE11(GPIO2_HP_BUTTON_A#)
TP_PLX_GPIO3: U1.AG12(GPIO3_HP_PWR_GOOD_A)
TP_PLX_GPIO4: U1.AE9(GPIO4_HP_PRSNT_A#)
TP_PLX_GPIO5: U1.AF18(GPIO5_HP_ATNLED_A#)
TP_PLX_GPIO6: U1.B2(GPIO6_HP_MRL_B#)
TP_PLX_GPIO7: U1.K13(GPIO7_HP_PWRFLT_B#)
TP_PLX_GPIO8: U1.G10(GPIO8_HP_BUTTON_B#)
TP_PLX_GPIO9: U1.G8(GPIO9_HP_PWR_GOOD_B)
TP_PLX_GPIO10: U1.J12(GPIO10_HP_PRSNT_B#)
TP_PLX_GPIO11: U1.A3(GPIO11_HP_ATNLED_B#)
TP_PLX_GPIO12: U1.AF27(GPIO12_HP_MRL_C#)
TP_PLX_GPIO13: U1.AF21(GPIO13_HP_PWRFLT_C#)
TP_PLX_GPIO14: U1.AF22(GPIO14_HP_BUTTON_C#)
TP_PLX_GPIO15: U1.AE23(GPIO15_HP_PWR_GOOD_C)
TP_PLX_GPIO16: U1.AH22(GPIO16_HP_PRSNT_C#)
TP_PLX_GPIO17: U1.AF26(GPIO17_HP_ATNLED_C#)
TP_PLX_GPIO18: U1.J19(GPIO18_HP_MRL_D#)
TP_PLX_GPIO19: U1.H25(GPIO19_HP_PWRFLT_D#)
TP_PLX_GPIO20: U1.K21(GPIO20_HP_BUTTON_D#)
TP_PLX_GPIO21: U1.H24(GPIO21_HP_PWR_GOOD_D)
TP_PLX_GPIO22: U1.J23(GPIO22_HP_PRSNT_D#)
TP_PLX_GPIO23: U1.K17(GPIO23_HP_ATNLED_D#)
TP_PLX_GPIO24: U1.T28(GPIO24_HP_MRL_E#)
TP_PLX_GPIO25: U1.AL34(GPIO25_HP_PWRFLT_E#)
TP_PLX_GPIO26: U1.AD27(GPIO26_HP_BUTTON_E#)
TP_PLX_GPIO27: U1.AM34(GPIO27_HP_PWR_GOOD_E)
TP_PLX_GPIO28: U1.AN33(GPIO28_HP_PRSNT_E#)
TP_PLX_GPIO29: U1.AA27(GPIO29_HP_ATNLED_E#)
TP_PLX_GPIO30: U1.C31(GPIO30_HP_MRL_F#)
TP_PLX_GPIO31: U1.B34(GPIO31_HP_PWRFLT_F#)
TP_PLX_GPIO32: U1.K27(GPIO32_HP_BUTTON_F#)
TP_PLX_GPIO33: U1.B33(GPIO33_HP_PWR_GOOD_F)
TP_PLX_GPIO34: U1.M27(GPIO34_HP_PRSNT_F#)
TP_PLX_GPIO35: U1.C33(GPIO35_HP_ATNLED_F#)
TP_PLX_JTAG_TDO: U1.AF13(JTAG_TDO)
TP_PLX_PORT_GOOD9_N: U1.AE24(PORT_GOOD9#_SHP_PERST9#_HP_CLKEN_C#)
TP_PLX_PORT_GOOD13_N: U1.H20(PORT_GOOD13#_SHP_PERST13#_HP_CLKEN_D#)
TP_PLX_PORT_GOOD17_N: U1.AM33(PORT_GOOD17#_SHP_PERST17#_HP_CLKEN_E#)
TP_PLX_PORT_GOOD21_N: U1.A32(PORT_GOOD21#_SHP_PERST21#_HP_CLKEN_F#)
TP_PLX_SHPC_INT_N: U1.AF9(SHPC_INT#)
TP_PLX_VS0_PERST_N: U1.K12(VS0_PERST#)
TP_PLX_VS1_PERST_N: U1.B3(VS1_PERST#)
TP_PLX_VS2_PERST_N: U1.AG23(VS2_PERST#)
TP_PLX_VS3_PERST_N: U1.J22(VS3_PERST#)
TP_RST_PLX_NT0_PERST_N: U1.AP2(PEX_NT0_PERST#)
TP_RST_PLX_NT1_PERST_N: U1.K14(PEX_NT1_PERST#)
TP_SMB_PLX1_I2C_SCL1_R: U1.AE12(I2C_SCL1)
TP_SMB_PLX1_I2C_SDA1_R: U1.AP3(I2C_SDA1)

Not connected (* = marked no-connect by the designer): U1 A2(NC0) A30(NC1) A33(NC2) AA6(NC29) AB1(NC30) AB2(NC31) AB4(NC32) AB5(NC33) AB27(PEX_REFCLK_SSCP18) AB28(PEX_REFCLK_SSCN18) AC6(NC34) AC27(NC35) AD29(NC36) AE7(PEX_REFCLK_SSCN1) AE8(PEX_REFCLK_SSCP1) AE27(PEX_REFCLK_SSCP17) AE28(PEX_REFCLK_SSCN17) AF14(NC37) AF17(NC38) AF20(NC39) AG9(PEX_REFCLK_SSCP3) AG26(NC40) AG27(PEX_REFCLK_SSCP16) AH7(PEX_REFCLK_SSCN2) AH8(PEX_REFCLK_SSCP2) AH9(PEX_REFCLK_SSCN3) AH26(NC41) AH27(PEX_REFCLK_SSCN16) AJ14(NC42) AL32(NC43) AM32(NC44) B32(NC3) D2(NC4) F17(NC5) G7(PEX_REFCLK_SSCN4) G11(PEX_REFCLK_SSCN15) G14(PEX_REFCLK_SSCN14) G18(PEX_REFCLK_SSCN13) G19(NC6) G20(NC7) G22(PEX_REFCLK_SSCN12) G26(PEX_REFCLK_SSCN23) G27(PEX_REFCLK_SSCP22) G28(PEX_REFCLK_SSCN22) H7(PEX_REFCLK_SSCP4) H11(PEX_REFCLK_SSCP15) H14(PEX_REFCLK_SSCP14) H18(PEX_REFCLK_SSCP13) H22(PEX_REFCLK_SSCP12) H26(PEX_REFCLK_SSCP23) J7(PEX_REFCLK_SSCN5) J8(PEX_REFCLK_SSCP5) J16(NC8) J25(NC9) K20(NC10) K24(NC11) K29(NC12) L7(PEX_REFCLK_SSCN6) L8(PEX_REFCLK_SSCP6) L27(PEX_REFCLK_SSCP21) L28(PEX_REFCLK_SSCN21) M8(NC13) N27(NC14) N30(NC15) N31(NC16) N33(NC17) N34(NC18) P6(NC19) P27(NC20) P29(NC21) R27(PEX_REFCLK_SSCP20) R28(PEX_REFCLK_SSCN20) R29(NC22) T7(PEX_REFCLK_SSCN7) T8(PEX_REFCLK_SSCP7) T27(NC23) U7(NC24) U27(NC25) W7(NC26) W27(PEX_REFCLK_SSCP19) W28(PEX_REFCLK_SSCN19) Y6(NC27) Y7(PEX_REFCLK_SSCN0) Y8(PEX_REFCLK_SSCP0) Y27(NC28)

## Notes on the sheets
sheet 1
- Big Sur _GPU LINKIN Board
- Cover Page
sheet 2
- P01  Cover Page
  P02  Index
  P03  PLX Switch-1 S0,PCIe[0..15]
  P04  PLX Switch-1 S1,PCIe[16..31]
  P05  PLX Switch-1 S2,PCIe[32..47]
  P06  PLX Switch-1 S3,PCIe[48..63]
  P07  PLX Switch-1 S4,PCIe[64..79]
  P08  PLX Switch-1 S5,PCIe[80..95]
  P09  PLX Switch-1 Mode Selection
  P10  PLX Switch-1 EEPROM & Port LED
  P11  PLX Switch-1 Straping
  P12  PLX Switch-1 Power
  P13  PLX Switch-1 VSS
  P14  PLX Switch-1 Decouping Cap
  P15  PLX Switch-2 S0,PCIe[0..15]
  P16  PLX Switch-2 S1,PCIe[16..31]
  P17  PLX Switch-2 S2,PCIe[32..47]
  P18  PLX Switch-2 S3,PCIe[48..63]
  P19  PLX Switch-2 S4,PCIe[64..79]
  P20  PLX Switch-2 S5,PCIe[80..95]
  P21  PLX Switch-2 Mode Selection
  P22  PLX Switch-2 EEPROM & Port LED
  P23  PLX Switch-2 Straping
  P24  PLX Switch-2 Power
  P25  PLX Switch-2 VSS
  P26  PLX Switch-2 Decouping Cap
  P27  PCIe Clock Generator-1
  P28  PCIe Clock Generator-2
  P29  MINI SAS HD Conn-A & B
  P30  MINI SAS HD Conn-C & D
  P31  PCIe x16 Slot-0
  P32  PCIe x16 Slot-1
  P33  PCIe x16 Slot-2
  P34  PCIe x16 Slot-3
- P35  PCIe x16 Slot-4
  P36  PCIe x16 Slot-5
  P37  PCIe x16 Slot-6
  P38  PCIe x16 Slot-7
  P39  MINI SAS HD for NIC 1&2
  P40  MINI SAS HD for NIC 3&4
  P41  Main Board Power Connector
  P42  GPU Power Connector
  P43  HDD B/P Power Connector
  P44  FRU & Temperature Sensor
  P45  SMBus & PMBus Connector
  P46  SMBus Multiplexer
  P47  PLX I2C Debug Header
  P48  P12V_STBY Hot Swap Controller
  P49  P12V_1 Hot Swap Controller-2
  P50  P12V_2 Hot Swap Controller-0
  P51  P12V   Hot Swap Controller-1
  P52  Hardware Monitor
  P53  Sytem Fan Module Connector
  P54  Sytem Fan Module
  P55  Power Control / GPU Throttle Circuit
  P56  Reset Control Circuit-1
  P57  Reset Control Circuit-2
  P58  P5V_STBY VR
  P59  P5V VR
  P60  P3V3_STBY VR
  P61  P3V3 VR
  P62  P1V8 VR for PLX-1
  P63  P1V8 VR for PLX-2
  P64  P0V9D VR for PLX-1
  P65  P0V9D VR for PLX-2
  P66  P0V9A VR for PLX-1
  P67  P0V9A VR for PLX-2
- P02  Index
sheet 9
- PEX8796
